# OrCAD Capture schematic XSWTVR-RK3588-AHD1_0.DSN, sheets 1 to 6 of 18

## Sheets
1 11 USB30 Port: size A3; rev: v1.0; company: yangdan; note: 11 USB30 Port; note: RK3588_AHD
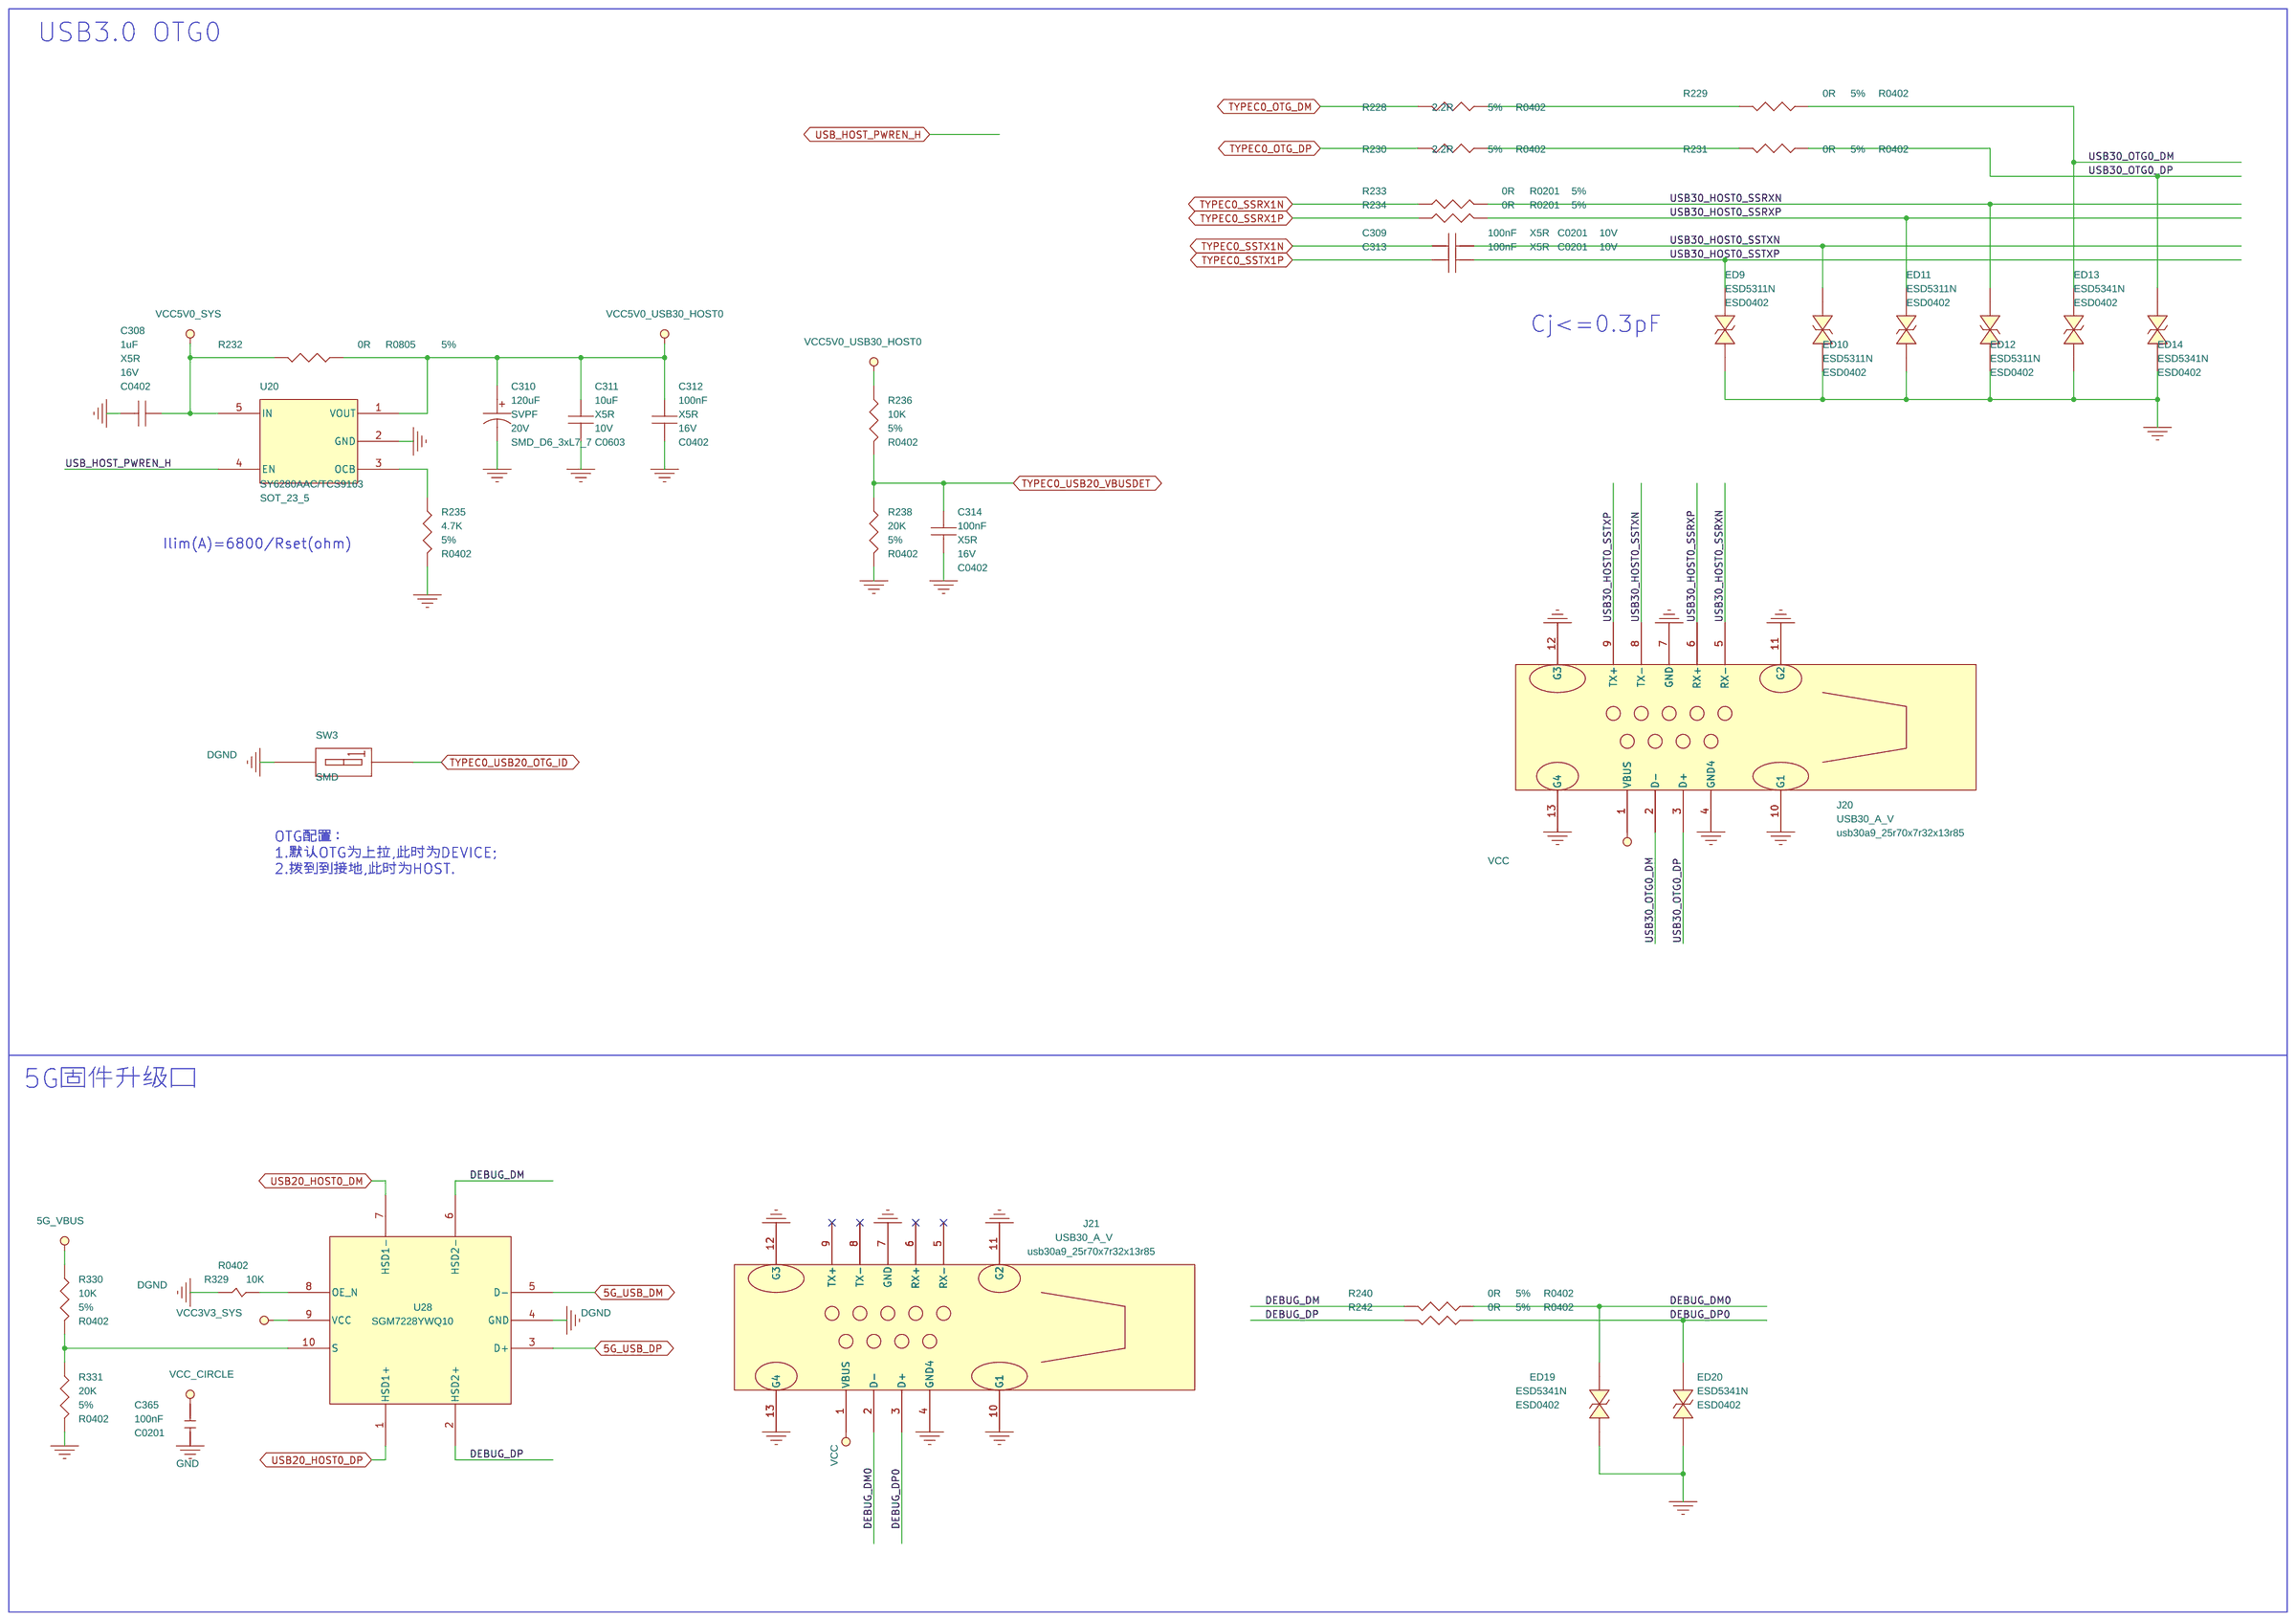
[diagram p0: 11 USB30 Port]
2 01 CORE_BROAD: size C; rev: V10; note: 01 CORE_BROAD
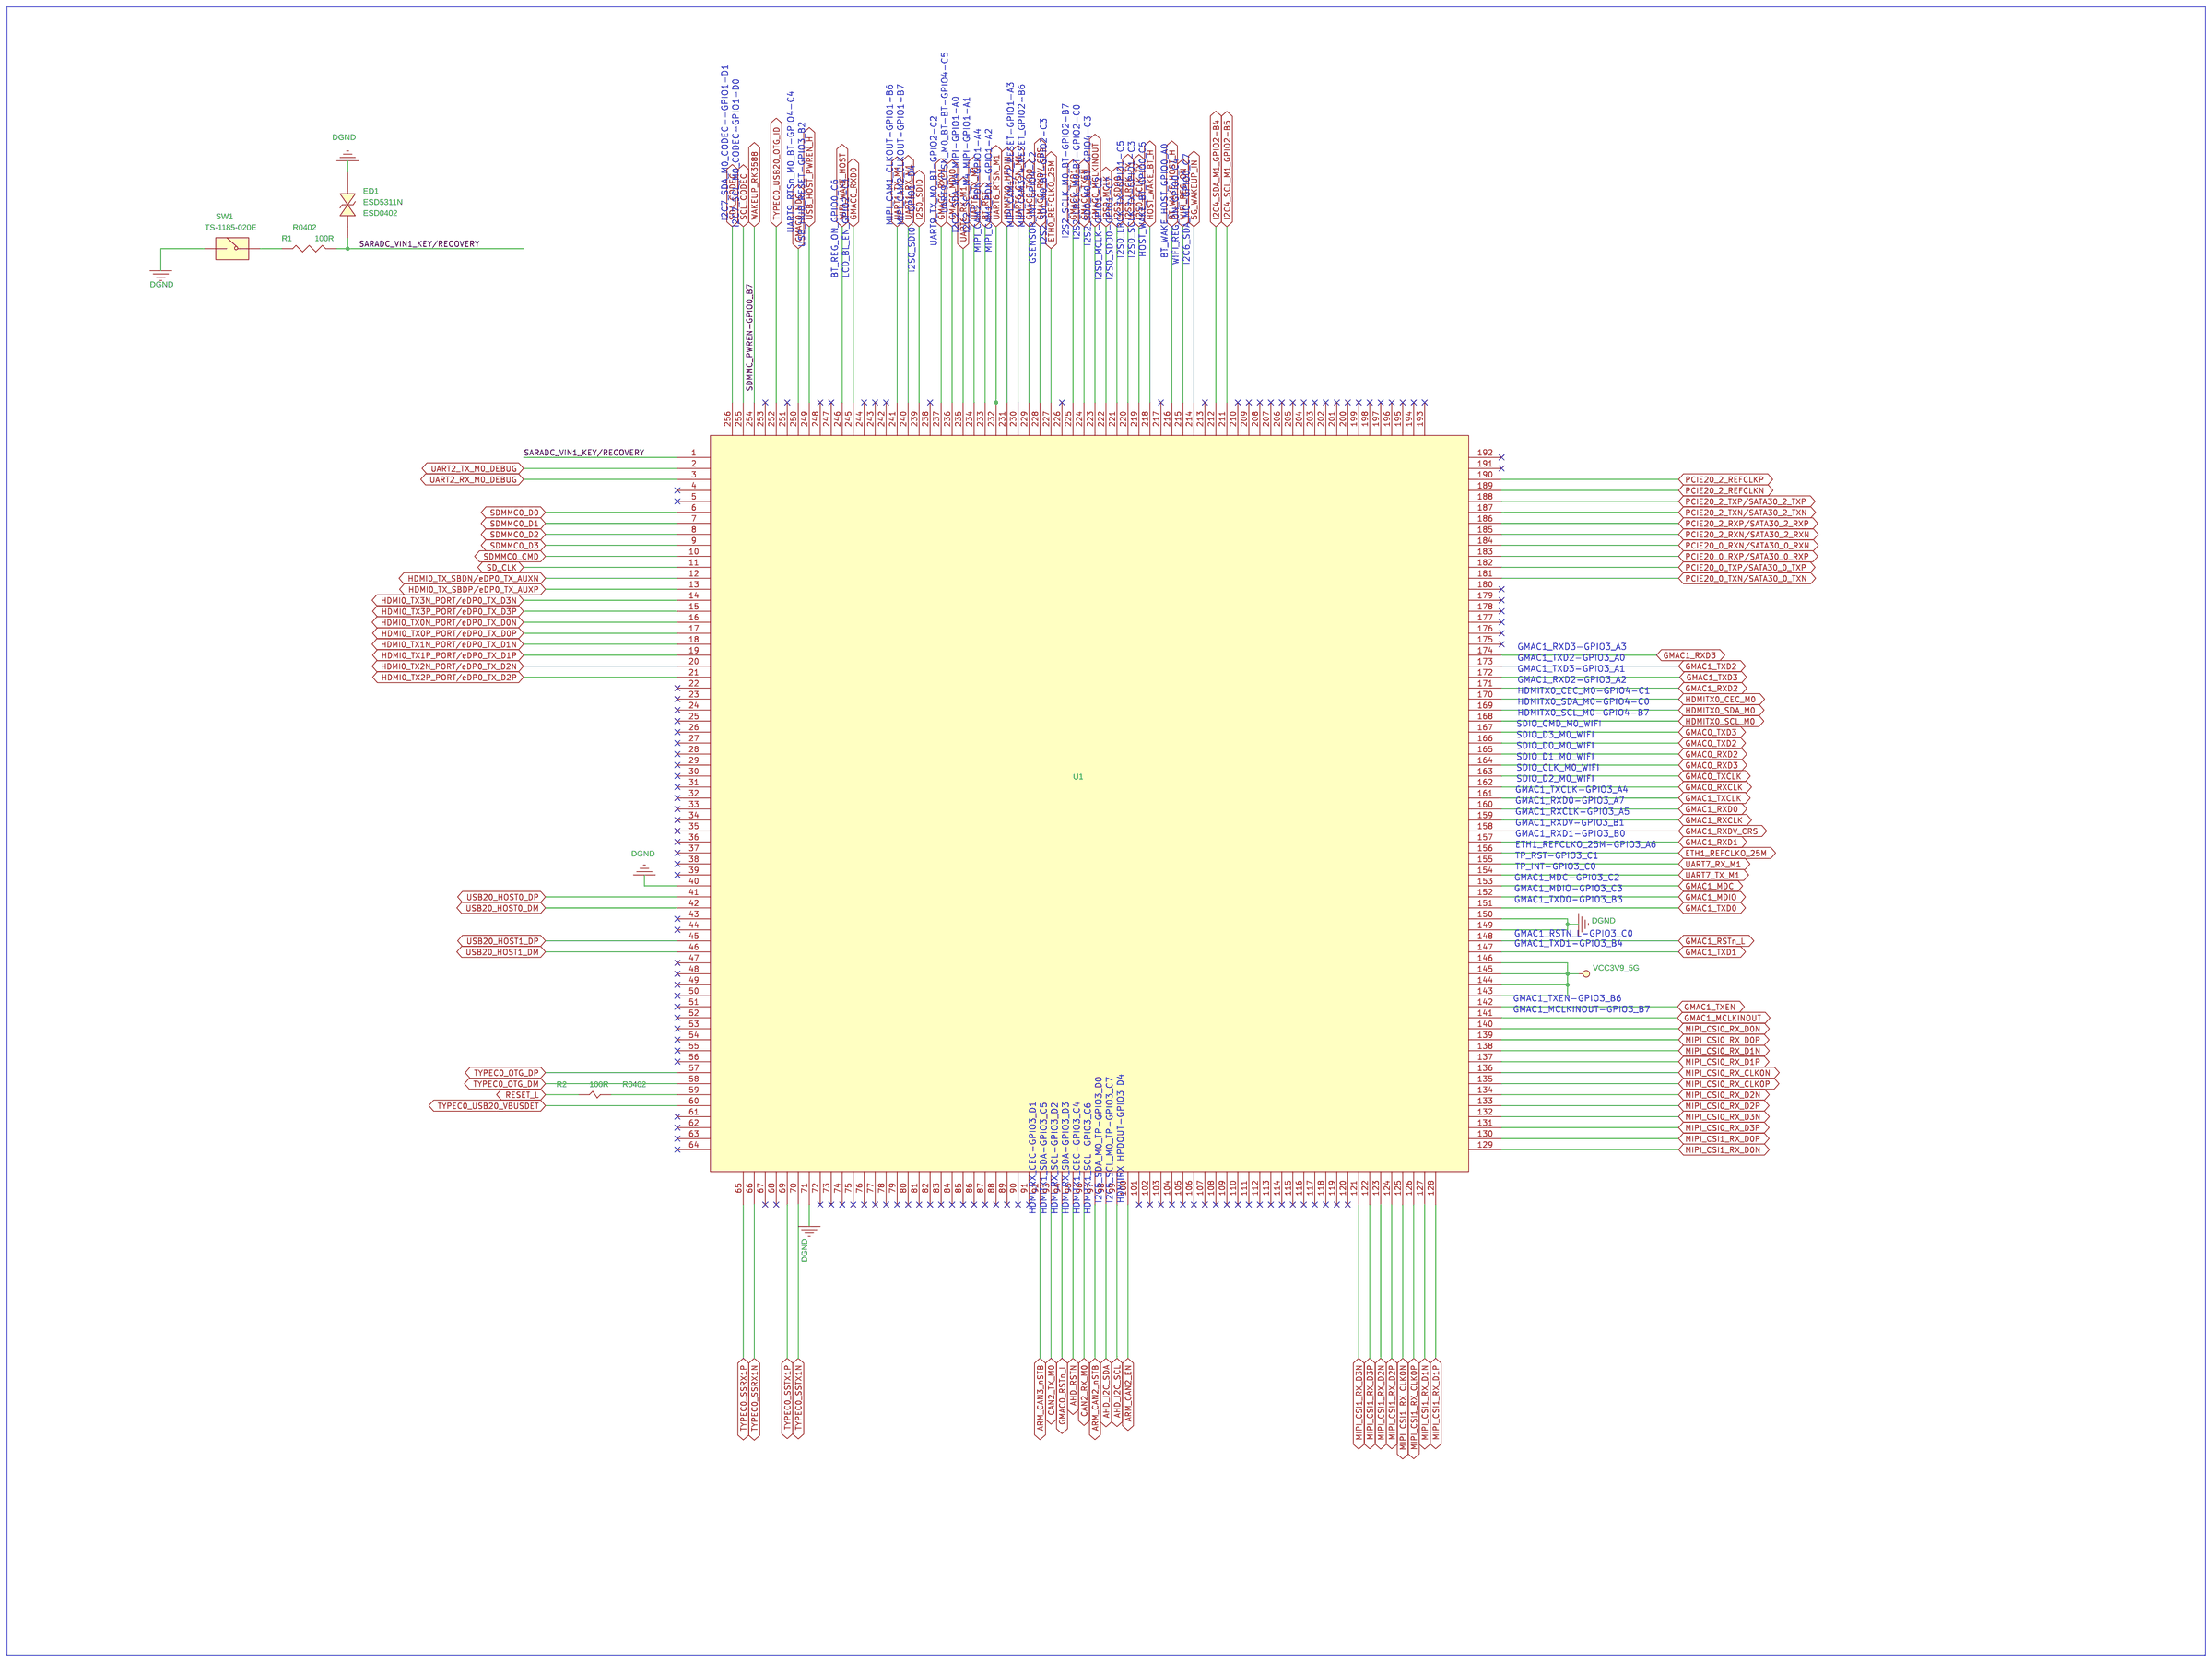
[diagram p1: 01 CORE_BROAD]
3 02 Power_DC IN: size Custom; note: 2 Power_DC IN
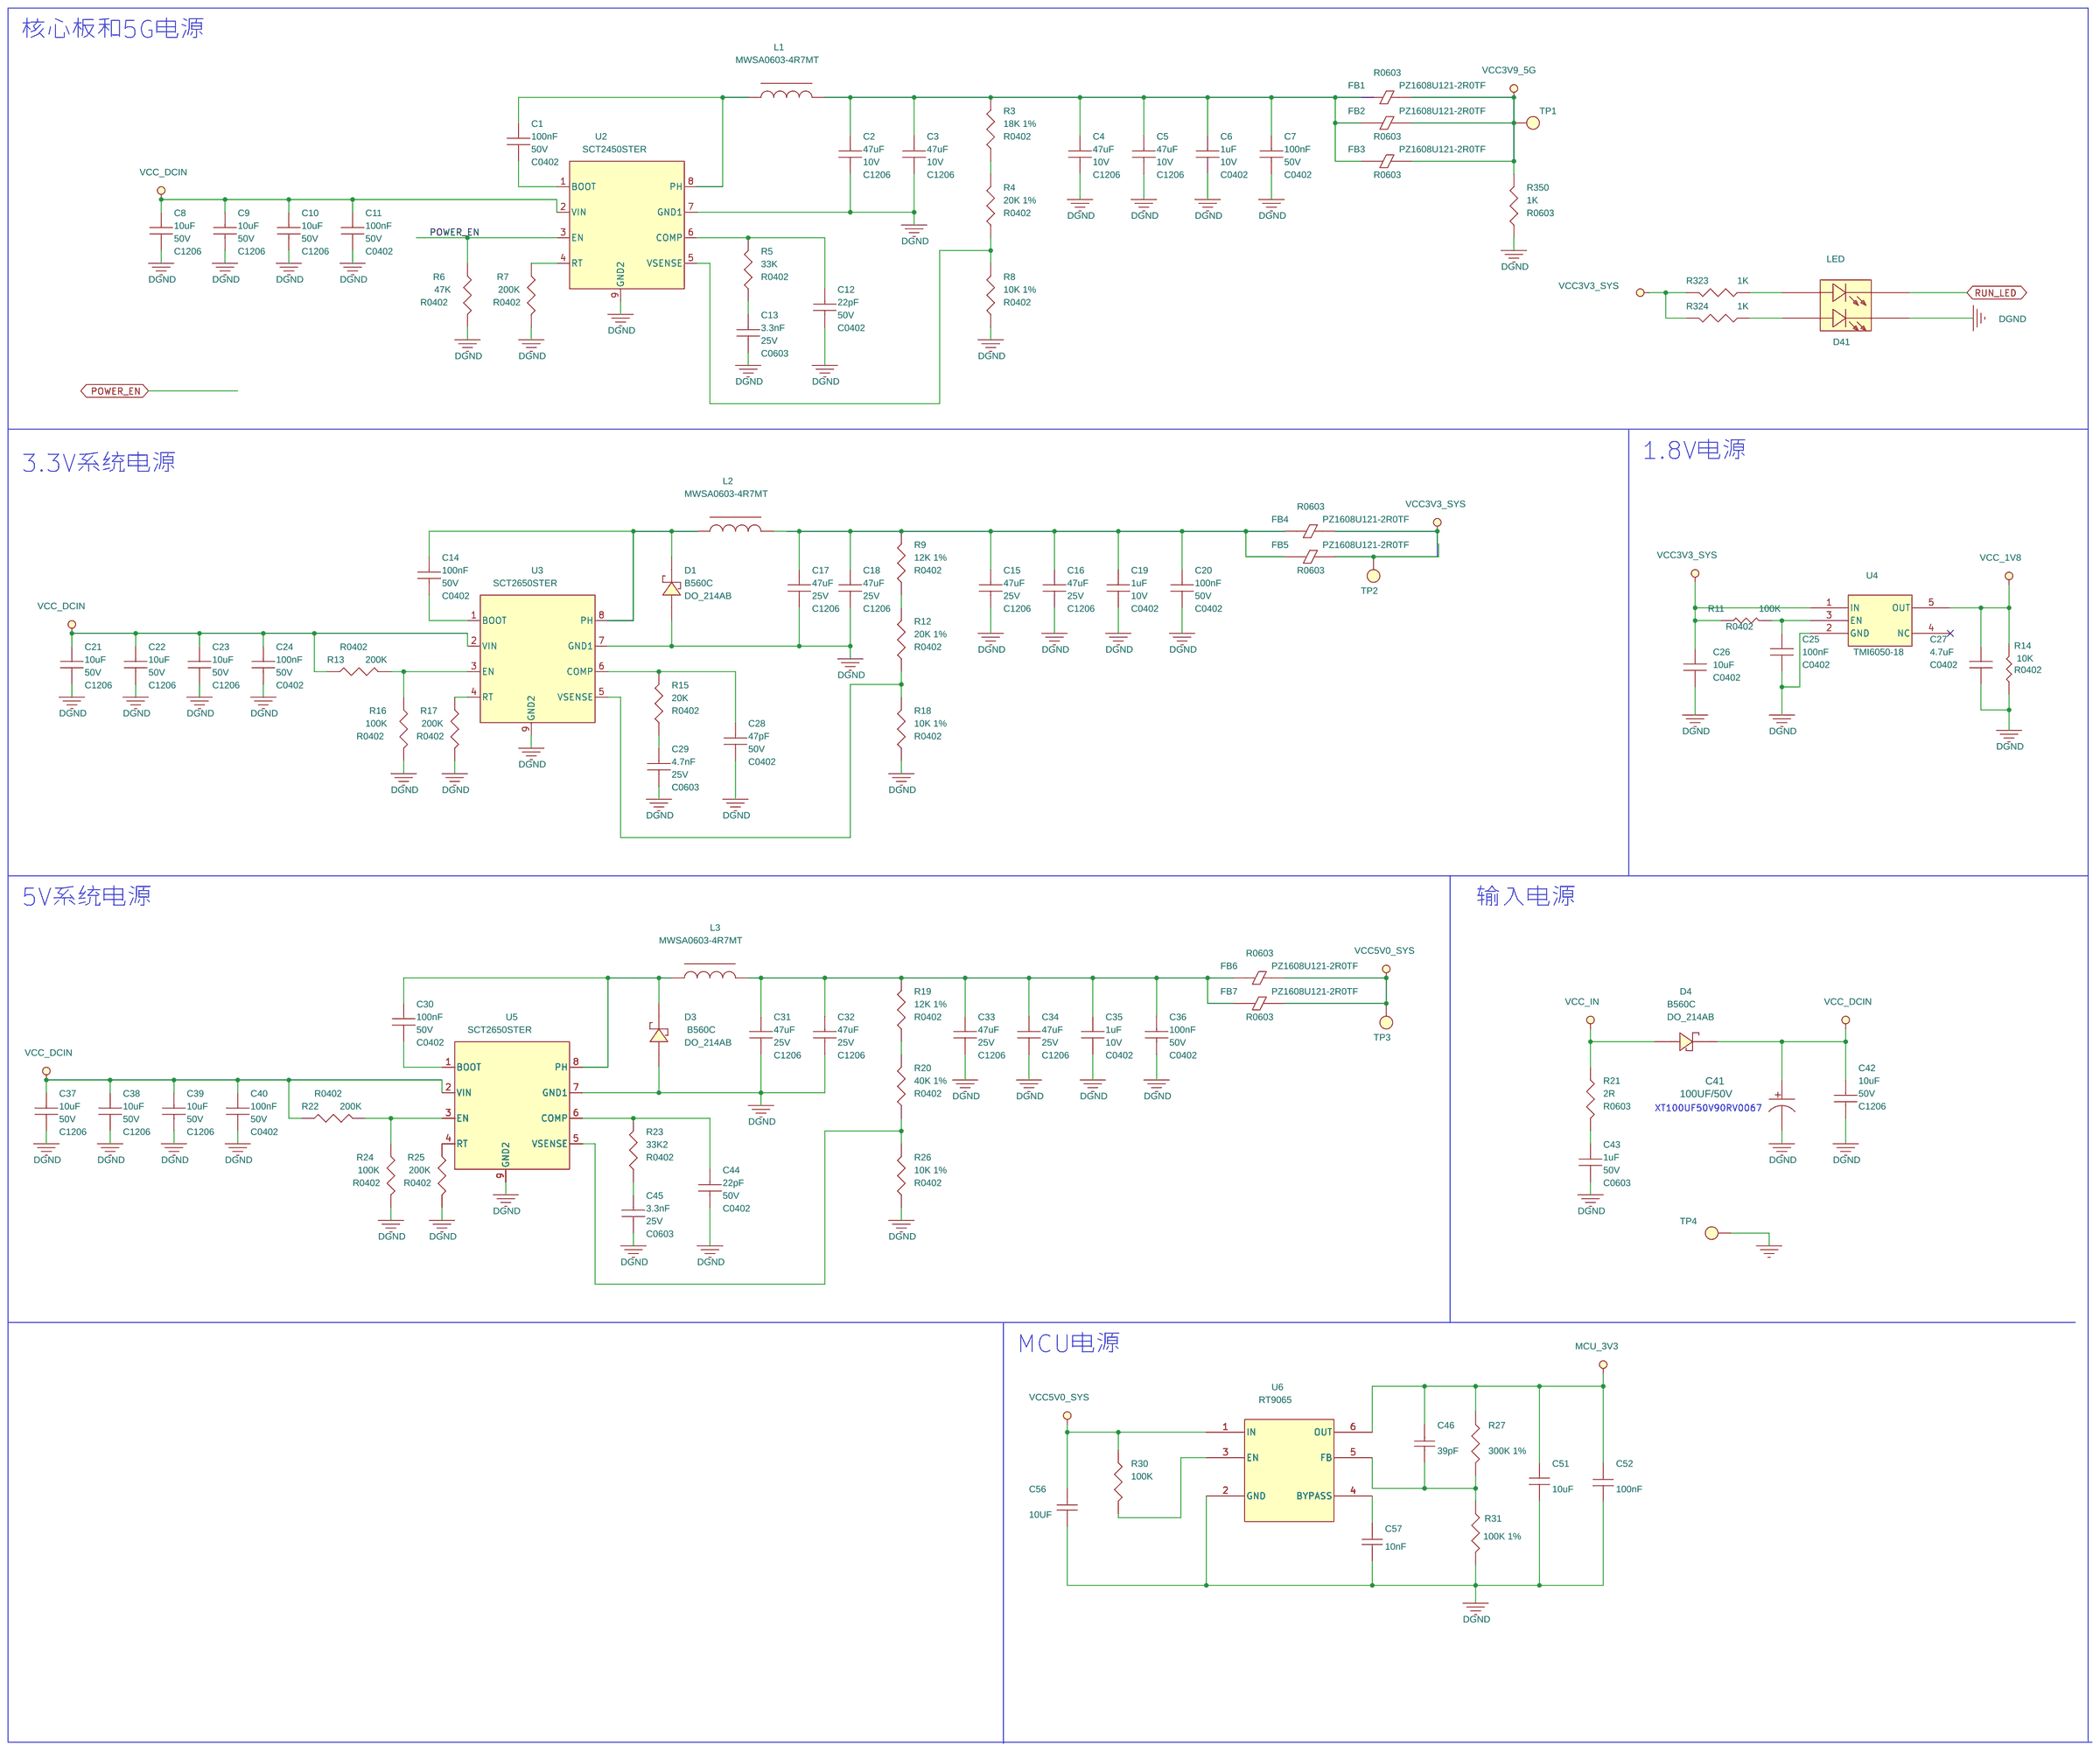
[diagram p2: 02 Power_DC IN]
4 03 MCU&MCU_CAN: size Custom; note: 03 MCU
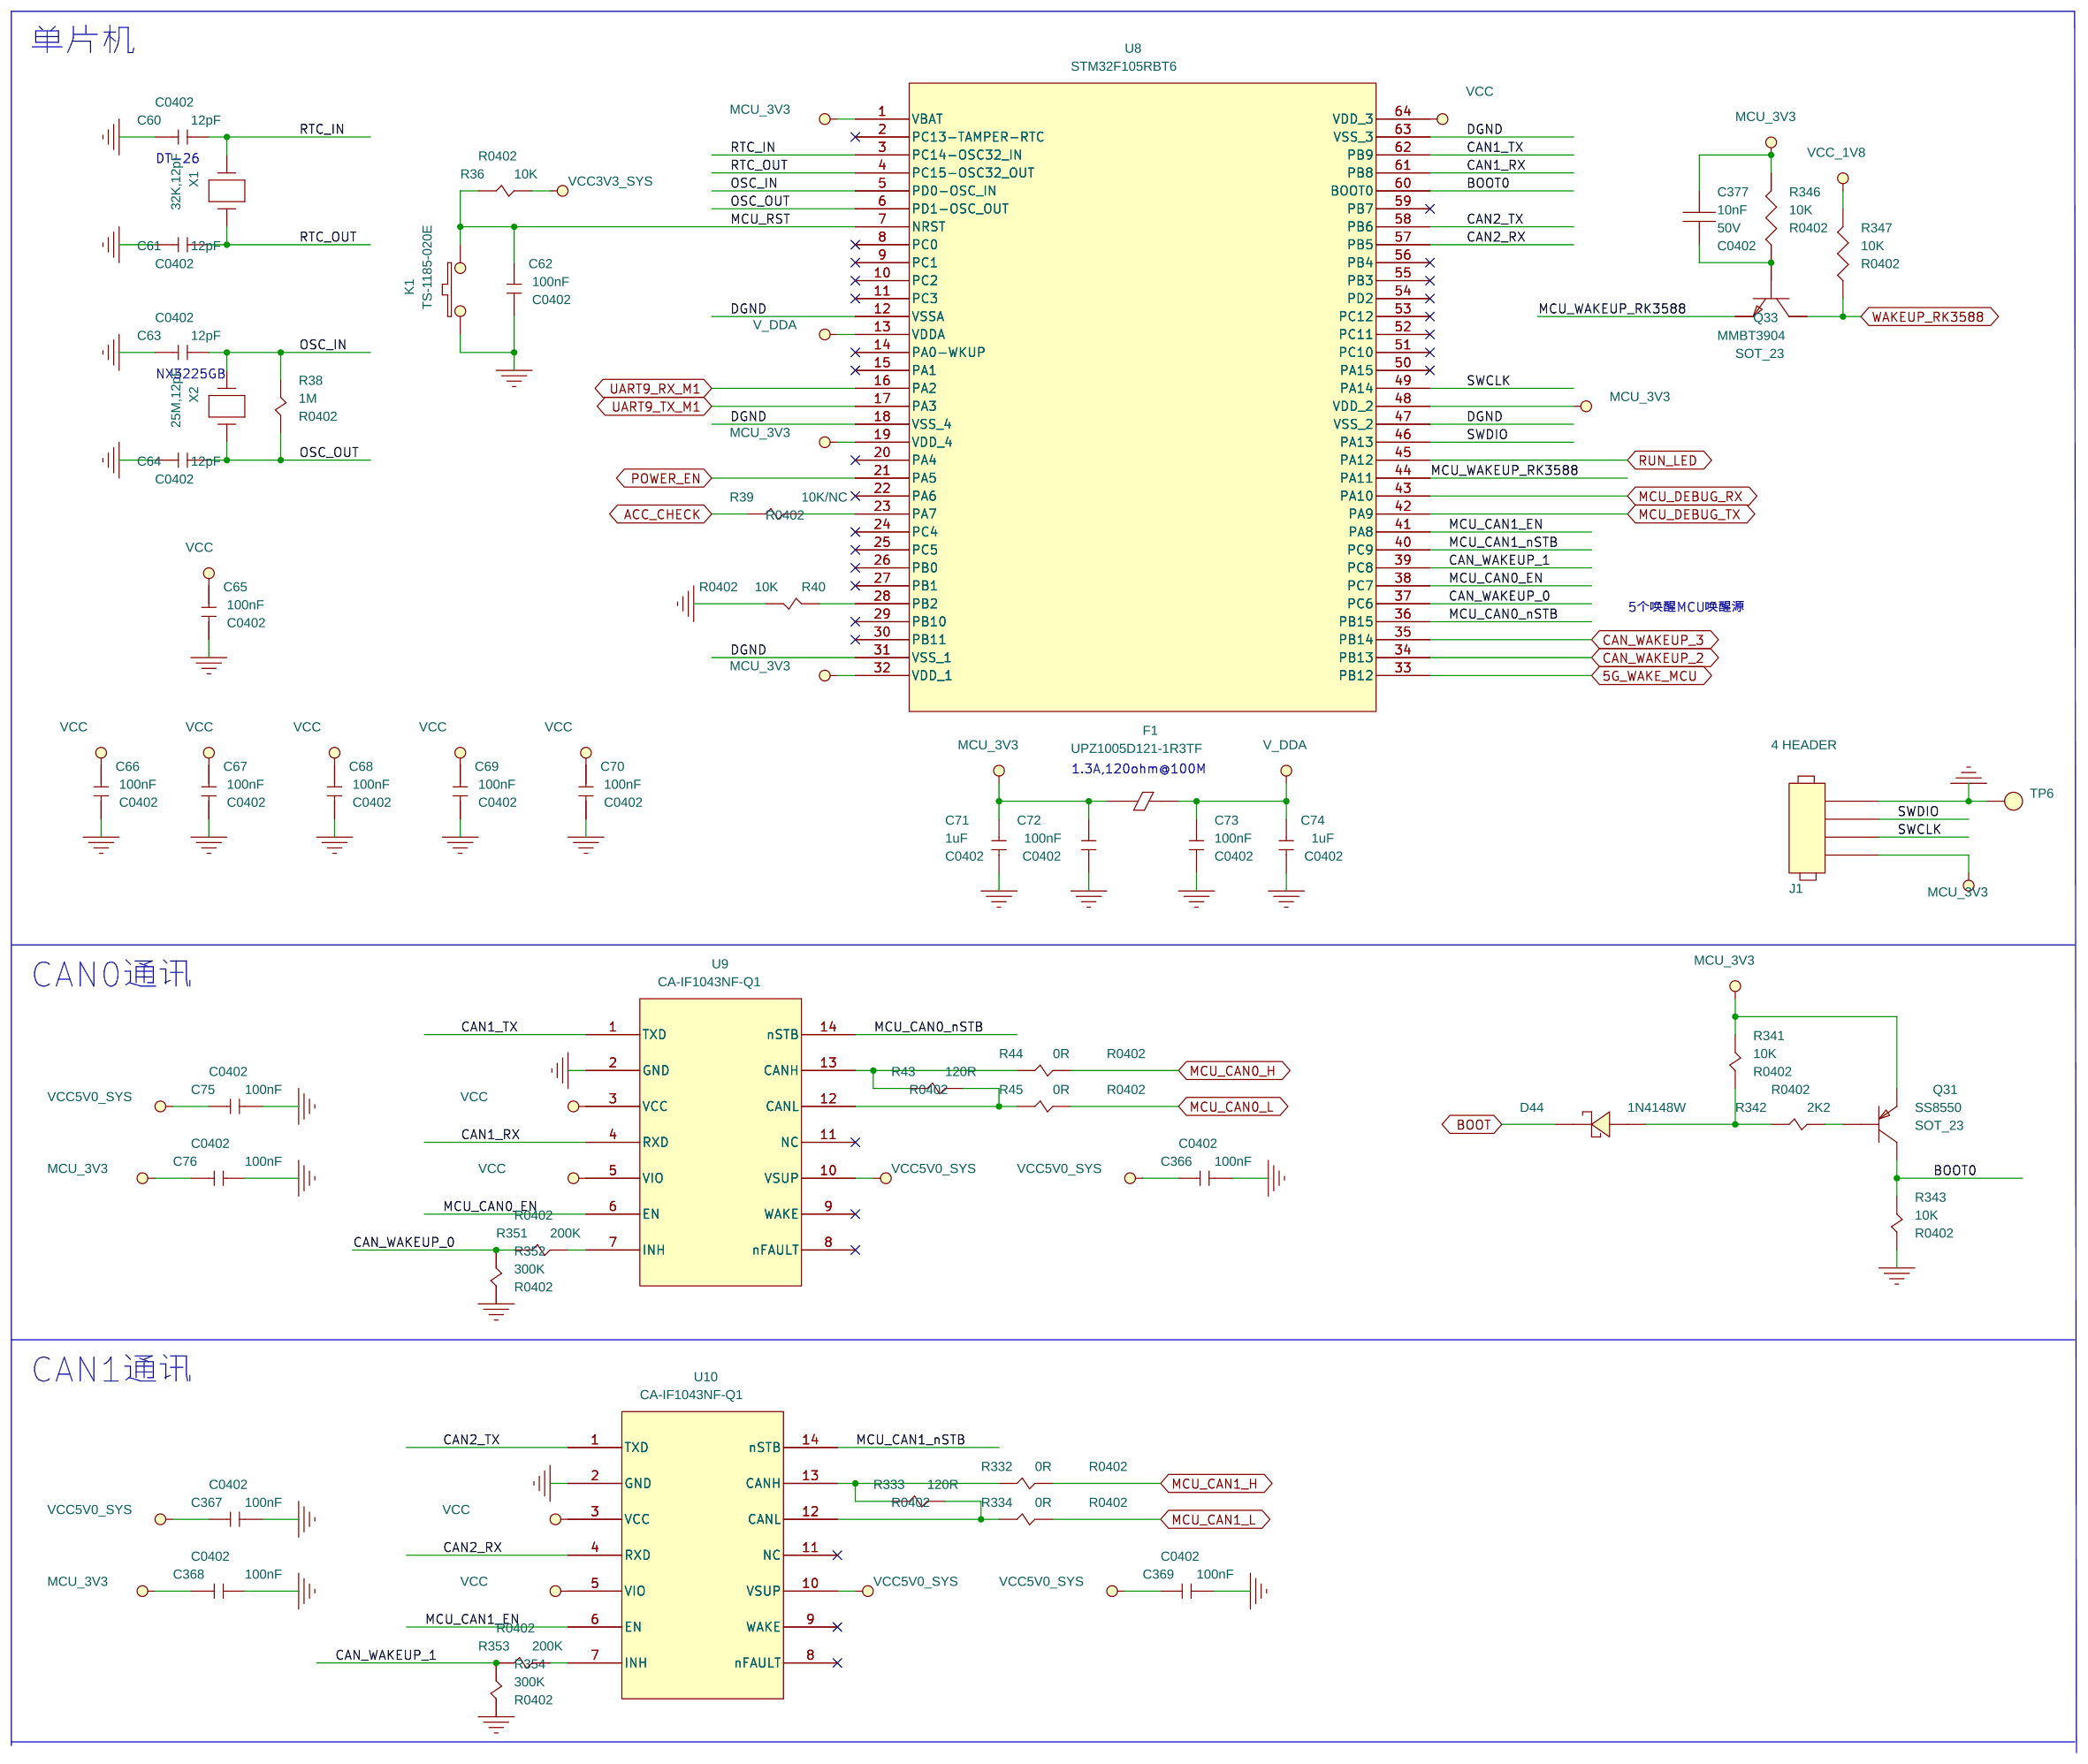
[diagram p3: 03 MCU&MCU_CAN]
5 04 M.2&5G: size Custom; note: 04 M.2&5G
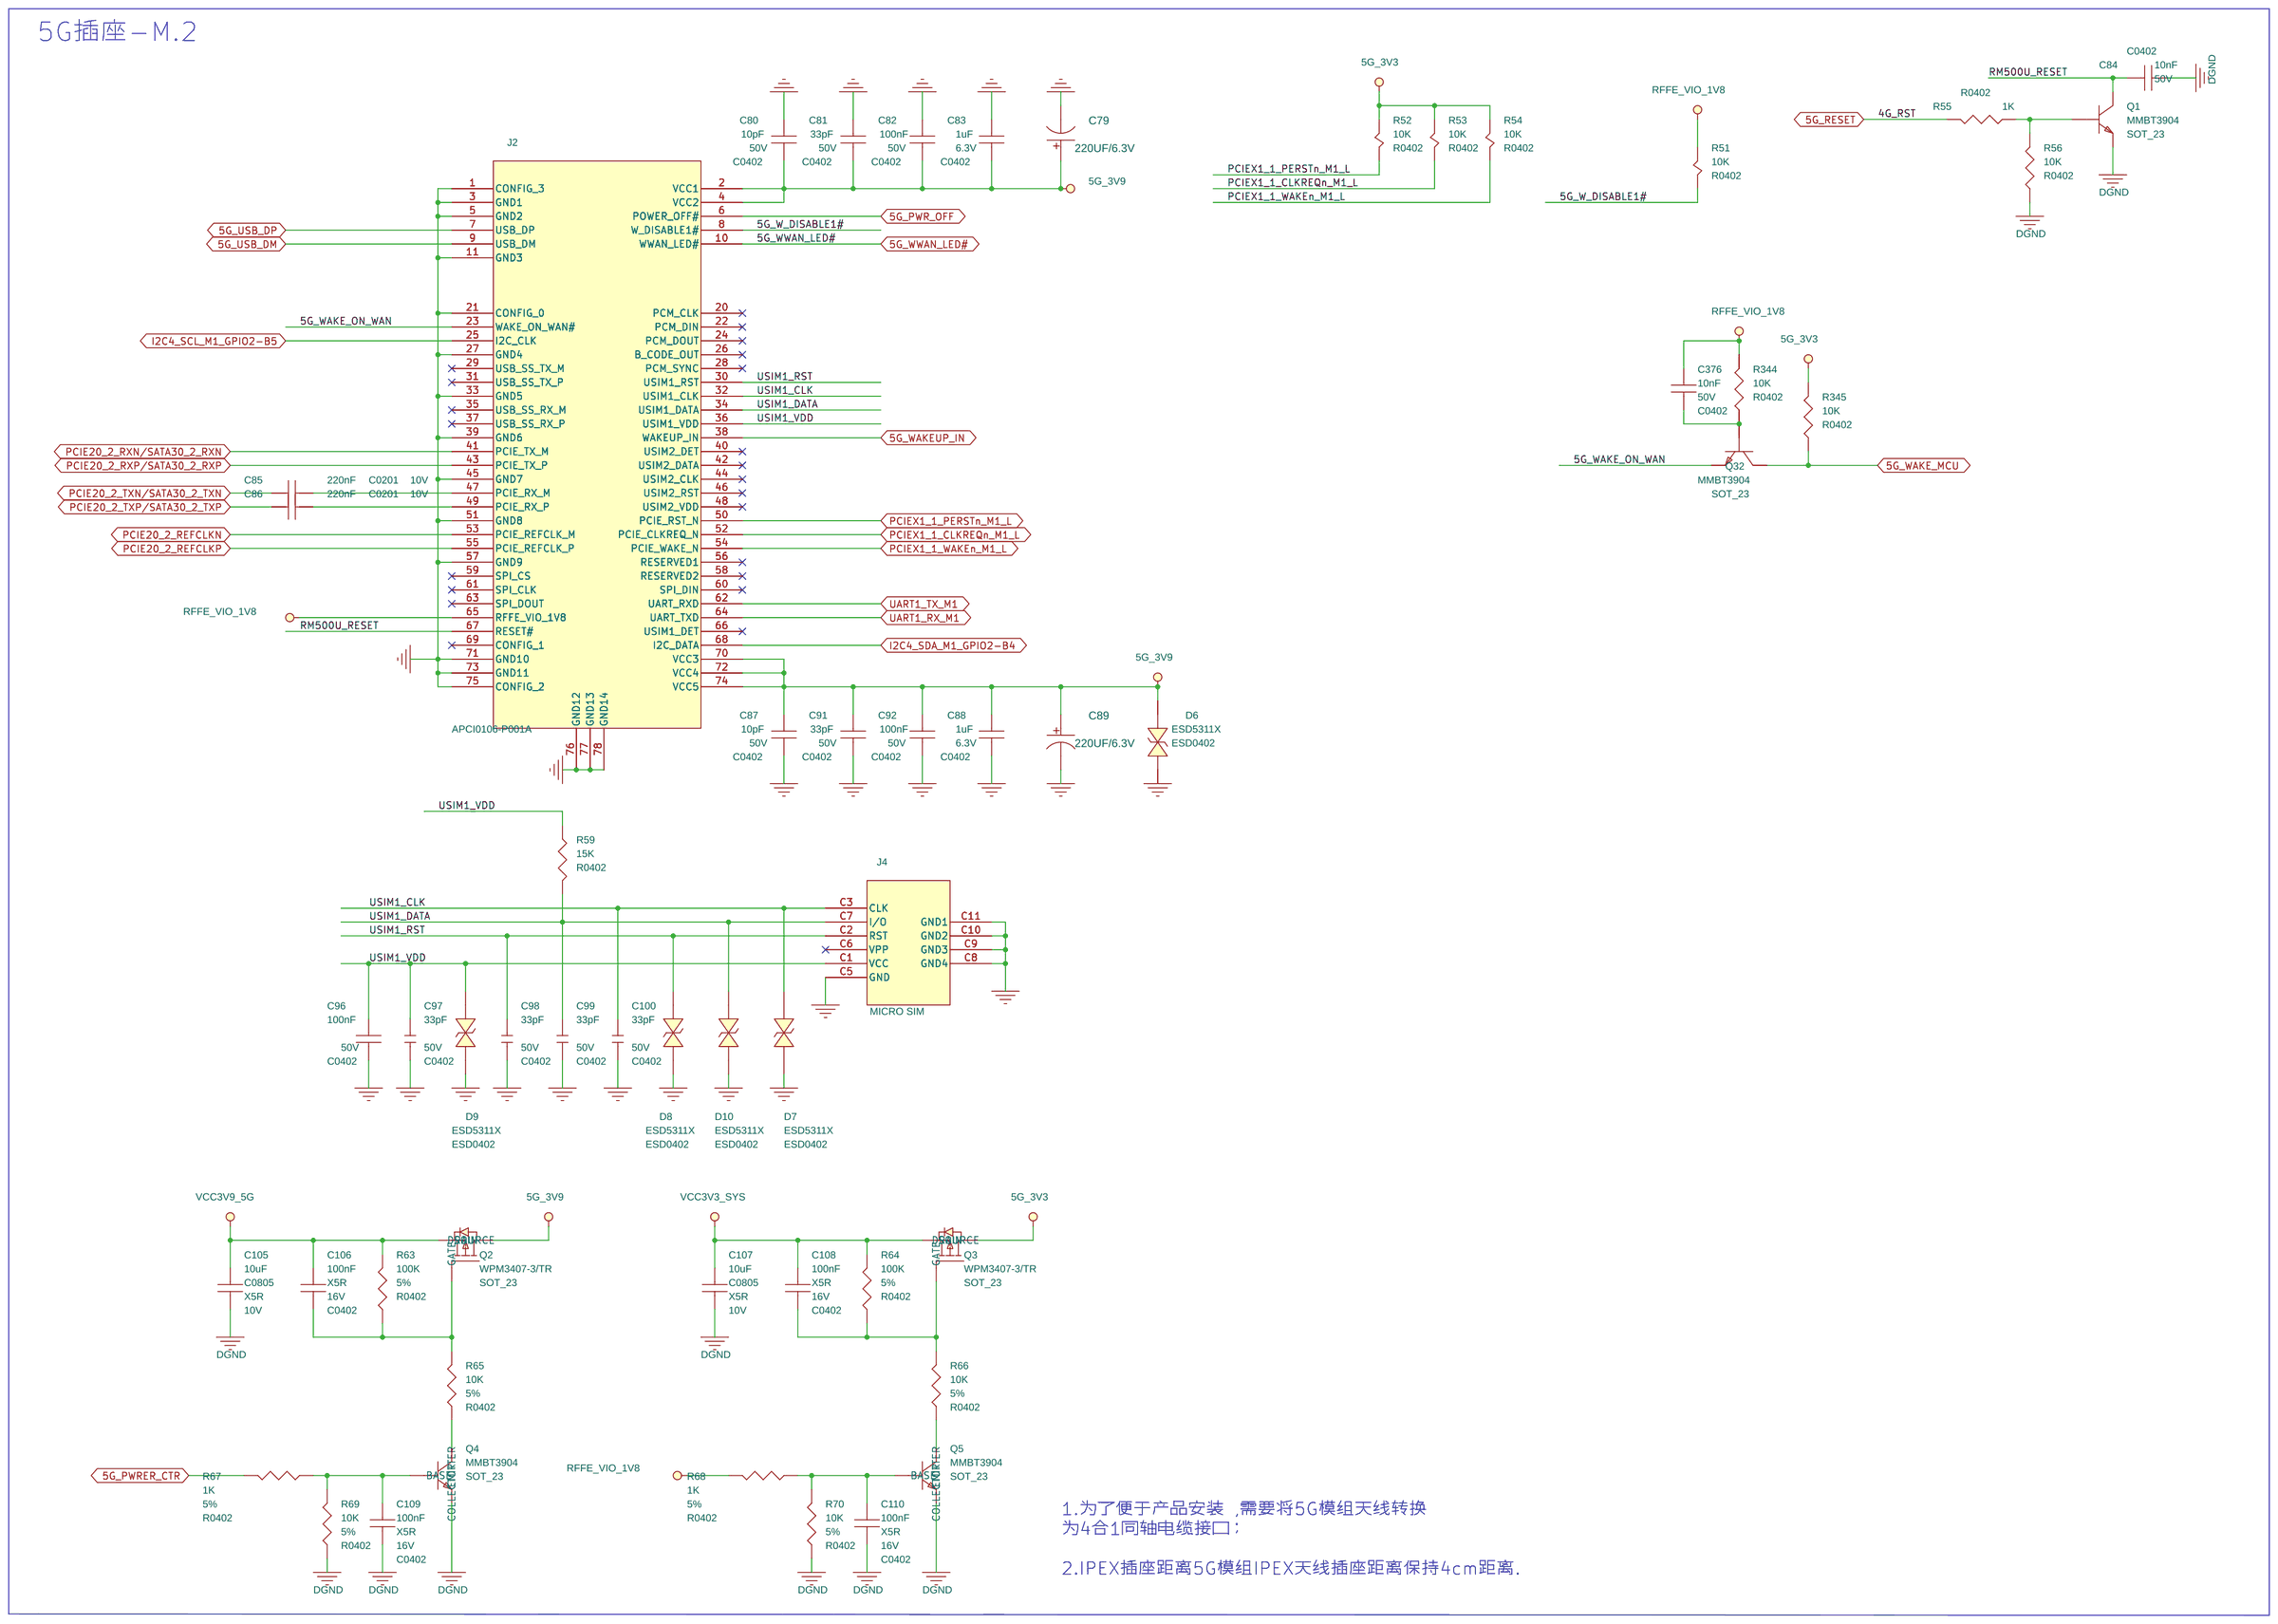
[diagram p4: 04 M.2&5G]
6 05 AHD-NVP6188A-01-04: size Custom; note: 05 AHD-NVP6188A
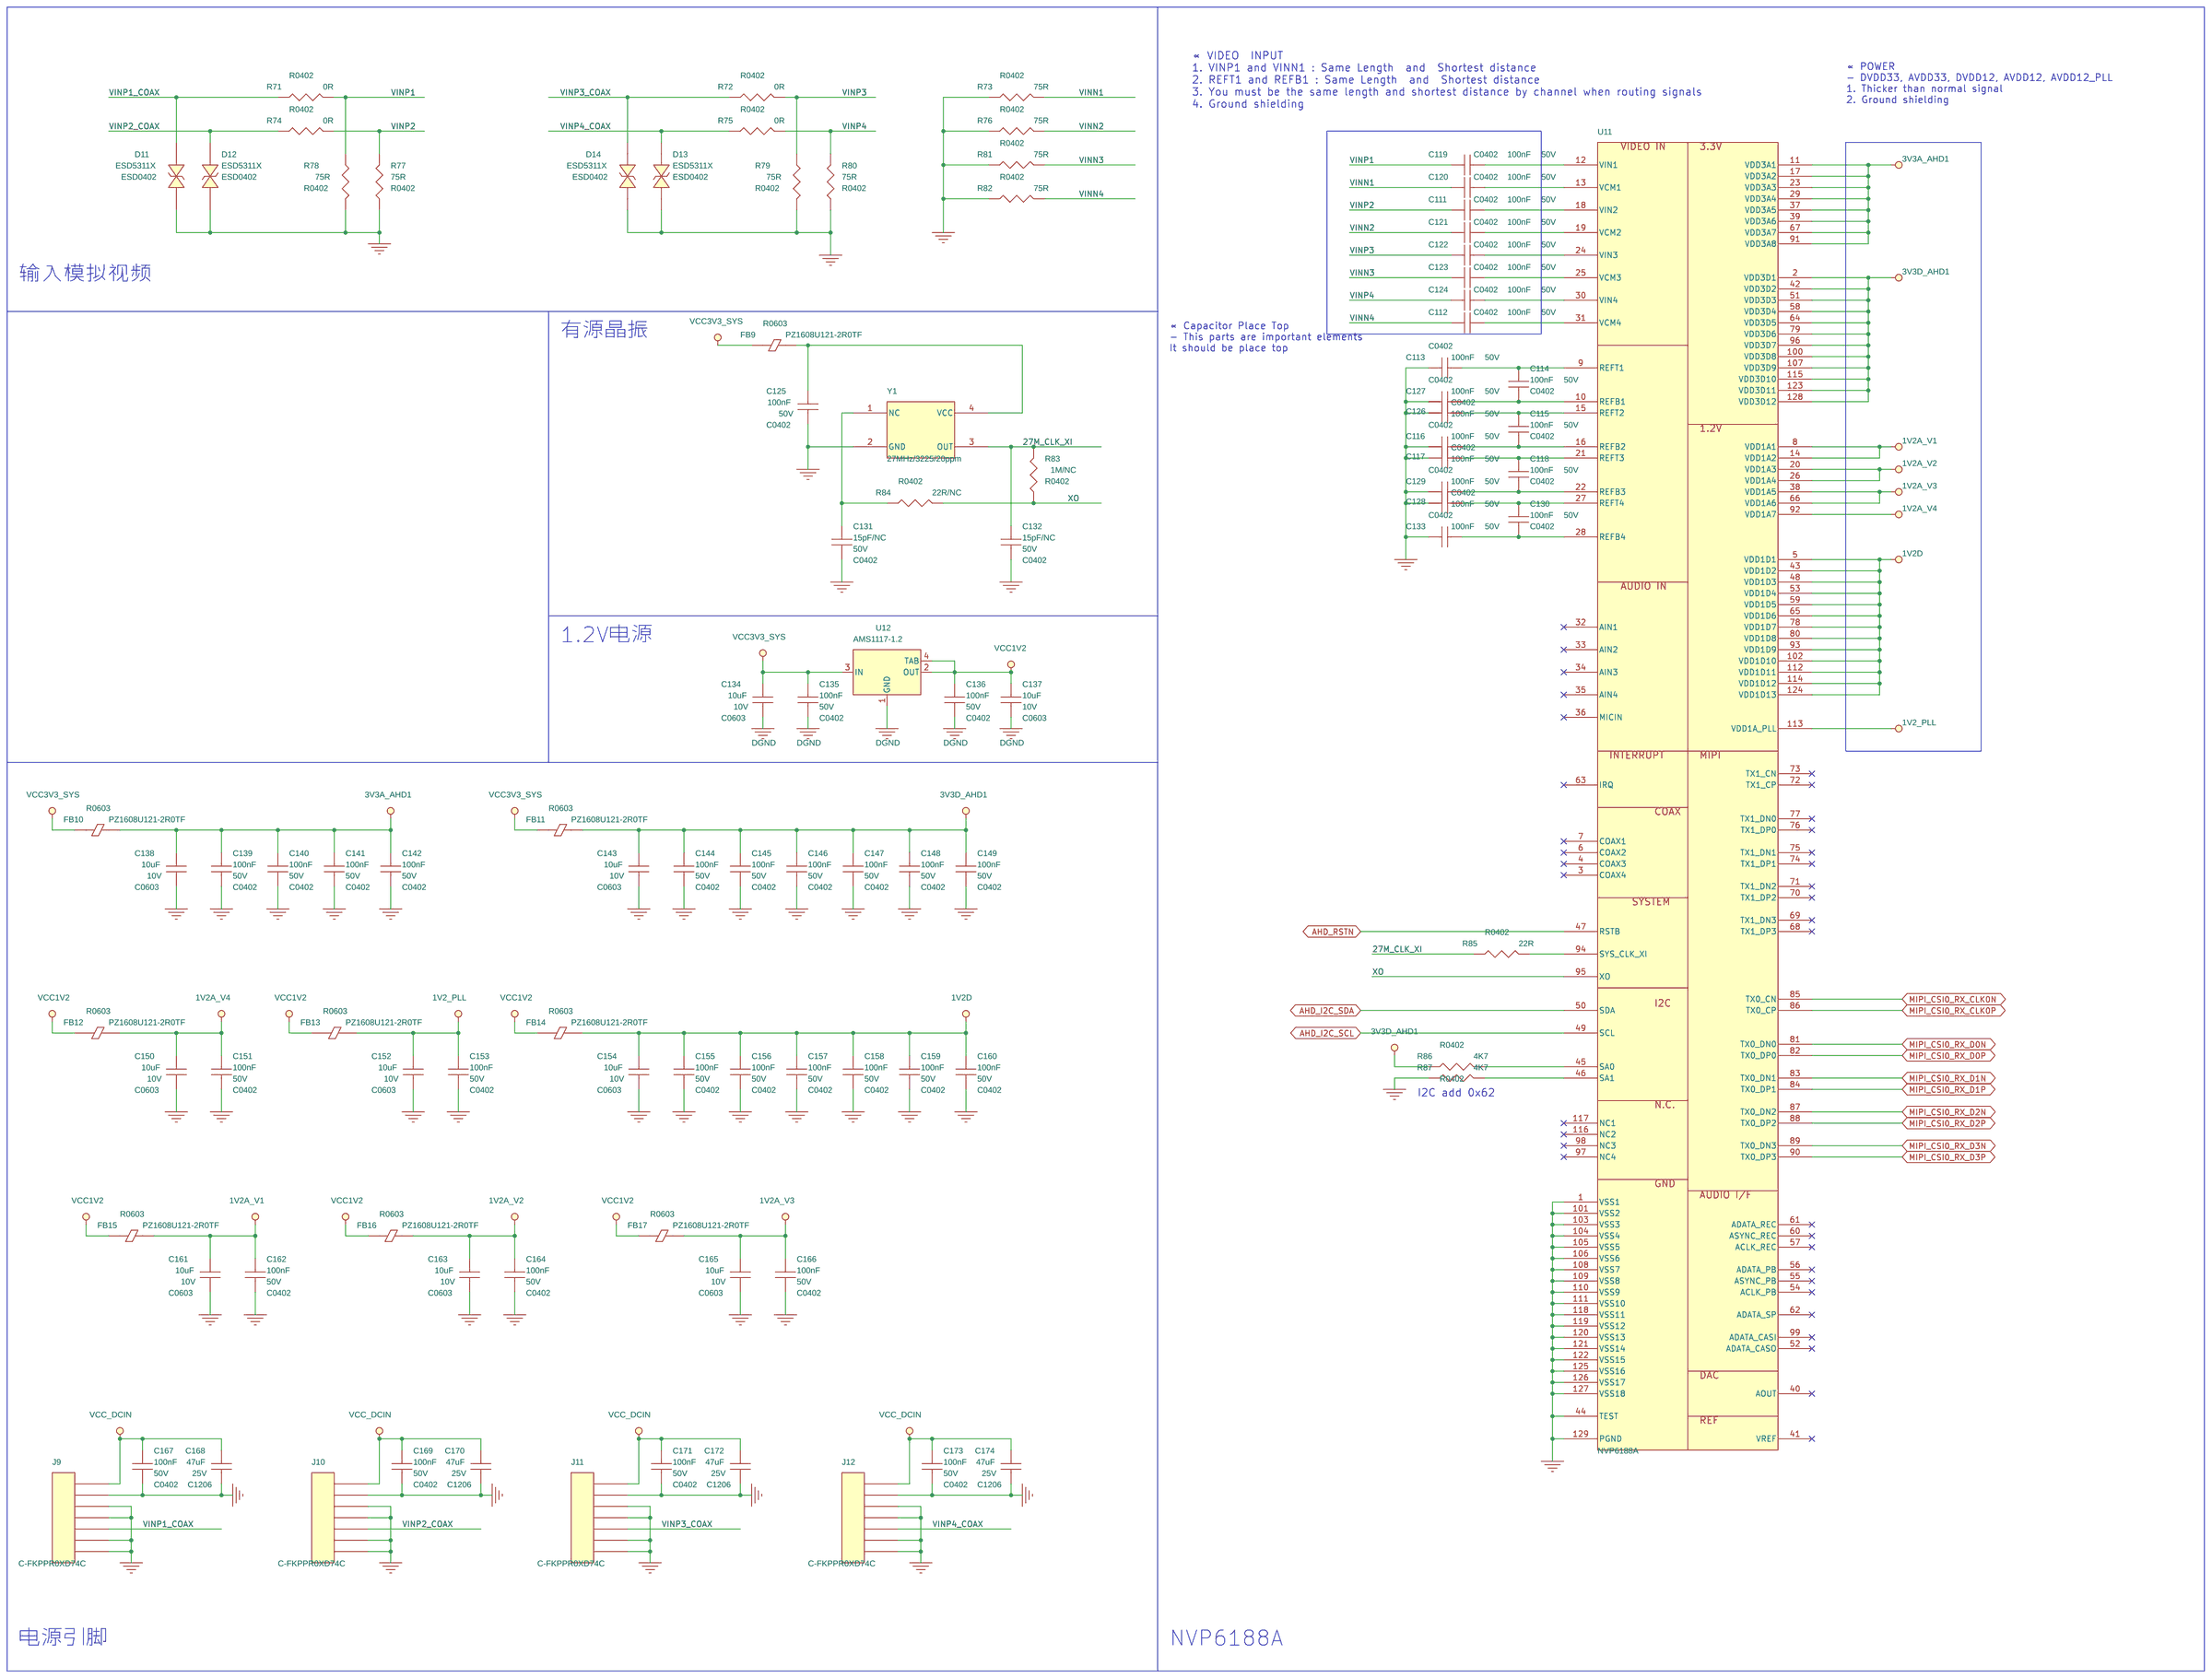
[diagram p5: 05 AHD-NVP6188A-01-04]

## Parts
sheet 01 CORE_BROAD
ED1  ESD5311N  [ESD0402]
R1  100R  [R0402]
R2  100R  [R0402]
SW1  TS-1185-020E  [SW_3p95mm_3p0mm]
U1  U1  [MODLE_65X65MM_256P]
sheet 02 Power_DC IN
C1  100nF  [C0402]
C2  47uF  [C1206]
C3  47uF  [C1206]
C4  47uF  [C1206]
C5  47uF  [C1206]
C6  1uF  [C0402]
C7  100nF  [C0402]
C8  10uF  [C1206]
C9  10uF  [C1206]
C10  10uF  [C1206]
C11  100nF  [C0402]
C12  22pF  [C0402]
C13  3.3nF  [C0603]
C14  100nF  [C0402]
C15  47uF  [C1206]
C16  47uF  [C1206]
C17  47uF  [C1206]
C18  47uF  [C1206]
C19  1uF  [C0402]
C20  100nF  [C0402]
C21  10uF  [C1206]
C22  10uF  [C1206]
C23  10uF  [C1206]
C24  100nF  [C0402]
C25  100nF  [C0402]
C26  10uF  [C0402]
C27  4.7uF  [C0402]
C28  47pF  [C0402]
C29  4.7nF  [C0603]
C30  100nF  [C0402]
C31  47uF  [C1206]
C32  47uF  [C1206]
C33  47uF  [C1206]
C34  47uF  [C1206]
C35  1uF  [C0402]
C36  100nF  [C0402]
C37  10uF  [C1206]
C38  10uF  [C1206]
C39  10uF  [C1206]
C40  100nF  [C0402]
C41  100UF/50V  [SMD_D8xL10_5mm]
C42  10uF  [C1206]
C43  1uF  [C0603]
C44  22pF  [C0402]
C45  3.3nF  [C0603]
C46  39pF  [C0402]
C51  10uF  [C0402]
C52  100nF  [C0402]
C56  10UF  [C0402]
C57  10nF  [C0402]
D1  B560C  [DO_214AB]
D3  B560C  [DO_214AB]
D4  B560C  [DO_214AB]
D41  LED  [LEDX2]
FB1  PZ1608U121-2R0TF  [R0603]
FB2  PZ1608U121-2R0TF  [R0603]
FB3  PZ1608U121-2R0TF  [R0603]
FB4  PZ1608U121-2R0TF  [R0603]
FB5  PZ1608U121-2R0TF  [R0603]
FB6  PZ1608U121-2R0TF  [R0603]
FB7  PZ1608U121-2R0TF  [R0603]
L1  MWSA0603-4R7MT  [L_6030]
L2  MWSA0603-4R7MT  [L_6030]
L3  MWSA0603-4R7MT  [L_6030]
R3  18K 1%  [R0402]
R4  20K 1%  [R0402]
R5  33K  [R0402]
R6  47K  [R0402]
R7  200K  [R0402]
R8  10K 1%  [R0402]
R9  12K 1%  [R0402]
R11  100K  [R0402]
R12  20K 1%  [R0402]
R13  200K  [R0402]
R14  10K  [R0402]
R15  20K  [R0402]
R16  100K  [R0402]
R17  200K  [R0402]
R18  10K 1%  [R0402]
R19  12K 1%  [R0402]
R20  40K 1%  [R0402]
R21  2R  [R0603]
R22  200K  [R0402]
R23  33K2  [R0402]
R24  100K  [R0402]
R25  200K  [R0402]
R26  10K 1%  [R0402]
R27  300K 1%  [R0402]
R30  100K  [R0402]
R31  100K 1%  [R0402]
R323  1K  [R0402]
R324  1K  [R0402]
R350  1K  [R0603]
TP1  TP  [TP_1_0]
TP2  TP  [TP_1_0]
TP3  TP  [TP_1_0]
TP4  TP  [TP_1_0]
U2  SCT2450STER  [IC_SOP8_PAD]
U3  SCT2650STER  [IC_SOP8_PAD]
U4  TMI6050-18  [SOT_23_5]
U5  SCT2650STER  [IC_SOP8_PAD]
U6  RT9065  [IC_SOT23_6]
sheet 03 MCU&MCU_CAN
C60  12pF  [C0402]
C61  12pF  [C0402]
C62  100nF  [C0402]
C63  12pF  [C0402]
C64  12pF  [C0402]
C65  100nF  [C0402]
C66  100nF  [C0402]
C67  100nF  [C0402]
C68  100nF  [C0402]
C69  100nF  [C0402]
C70  100nF  [C0402]
C71  1uF  [C0402]
C72  100nF  [C0402]
C73  100nF  [C0402]
C74  1uF  [C0402]
C75  100nF  [C0402]
C76  100nF  [C0402]
C366  100nF  [C0402]
C367  100nF  [C0402]
C368  100nF  [C0402]
C369  100nF  [C0402]
C377  10nF  [C0402]
D44  1N4148W  [SOD_123]
F1  UPZ1005D121-1R3TF  [R0402]
J1  4 HEADER  [SOCKET_4P_2P54]
K1  TS-1185-020E  [SW_3p95mm_3p0mm]
Q31  SS8550  [SOT_23]
Q33  MMBT3904  [SOT_23]
R36  10K  [R0402]
R38  1M  [R0402]
R39  10K/NC  [R0402]
R40  10K  [R0402]
R43  120R  [R0402]
R44  0R  [R0402]
R45  0R  [R0402]
R332  0R  [R0402]
R333  120R  [R0402]
R334  0R  [R0402]
R341  10K  [R0402]
R342  2K2  [R0402]
R343  10K  [R0402]
R346  10K  [R0402]
R347  10K  [R0402]
R351  200K  [R0402]
R352  300K  [R0402]
R353  200K  [R0402]
R354  300K  [R0402]
TP6  TP  [TP_1_0]
U8  STM32F105RBT6  [IC_QFN64_STM32]
U9  CA-IF1043NF-Q1  [IC_SOIC_14]
U10  CA-IF1043NF-Q1  [IC_SOIC_14]
X1  32K,12pF  [X_3215_2P]
X2  25M,12pF  [X_3225_2P]
sheet 04 M.2&5G
C79  220UF/6.3V  [T_3528]
C80  10pF  [C0402]
C81  33pF  [C0402]
C82  100nF  [C0402]
C83  1uF  [C0402]
C84  10nF  [C0402]
C85  220nF  [C0201]
C86  220nF  [C0201]
C87  10pF  [C0402]
C88  1uF  [C0402]
C89  220UF/6.3V  [T_3528]
C91  33pF  [C0402]
C92  100nF  [C0402]
C96  100nF  [C0402]
C97  33pF  [C0402]
C98  33pF  [C0402]
C99  33pF  [C0402]
C100  33pF  [C0402]
C105  10uF  [C0805]
C106  100nF  [C0402]
C107  10uF  [C0805]
C108  100nF  [C0402]
C109  100nF  [C0402]
C110  100nF  [C0402]
C376  10nF  [C0402]
D6  ESD5311X  [ESD0402]
D7  ESD5311X  [ESD0402]
D8  ESD5311X  [ESD0402]
D9  ESD5311X  [ESD0402]
D10  ESD5311X  [ESD0402]
J2  APCI0106-P001A  [M2_M_KEY]
J4  MICRO SIM  [SIM_002_P6]
Q1  MMBT3904  [SOT_23]
Q2  WPM3407-3/TR  [SOT_23]
Q3  WPM3407-3/TR  [SOT_23]
Q4  MMBT3904  [SOT_23]
Q5  MMBT3904  [SOT_23]
Q32  MMBT3904  [SOT_23]
R51  10K  [R0402]
R52  10K  [R0402]
R53  10K  [R0402]
R54  10K  [R0402]
R55  1K  [R0402]
R56  10K  [R0402]
R59  15K  [R0402]
R63  100K  [R0402]
R64  100K  [R0402]
R65  10K  [R0402]
R66  10K  [R0402]
R67  1K  [R0402]
R68  1K  [R0402]
R69  10K  [R0402]
R70  10K  [R0402]
R344  10K  [R0402]
R345  10K  [R0402]
sheet 05 AHD-NVP6188A-01-04
C111  100nF  [C0402]
C112  100nF  [C0402]
C113  100nF  [C0402]
C114  100nF  [C0402]
C115  100nF  [C0402]
C116  100nF  [C0402]
C117  100nF  [C0402]
C118  100nF  [C0402]
C119  100nF  [C0402]
C120  100nF  [C0402]
C121  100nF  [C0402]
C122  100nF  [C0402]
C123  100nF  [C0402]
C124  100nF  [C0402]
C125  100nF  [C0402]
C126  100nF  [C0402]
C127  100nF  [C0402]
C128  100nF  [C0402]
C129  100nF  [C0402]
C130  100nF  [C0402]
C131  15pF/NC  [C0402]
C132  15pF/NC  [C0402]
C133  100nF  [C0402]
C134  10uF  [C0603]
C135  100nF  [C0402]
C136  100nF  [C0402]
C137  10uF  [C0603]
C138  10uF  [C0603]
C139  100nF  [C0402]
C140  100nF  [C0402]
C141  100nF  [C0402]
C142  100nF  [C0402]
C143  10uF  [C0603]
C144  100nF  [C0402]
C145  100nF  [C0402]
C146  100nF  [C0402]
C147  100nF  [C0402]
C148  100nF  [C0402]
C149  100nF  [C0402]
C150  10uF  [C0603]
C151  100nF  [C0402]
C152  10uF  [C0603]
C153  100nF  [C0402]
C154  10uF  [C0603]
C155  100nF  [C0402]
C156  100nF  [C0402]
C157  100nF  [C0402]
C158  100nF  [C0402]
C159  100nF  [C0402]
C160  100nF  [C0402]
C161  10uF  [C0603]
C162  100nF  [C0402]
C163  10uF  [C0603]
C164  100nF  [C0402]
C165  10uF  [C0603]
C166  100nF  [C0402]
C167  100nF  [C0402]
C168  47uF  [C1206]
C169  100nF  [C0402]
C170  47uF  [C1206]
C171  100nF  [C0402]
C172  47uF  [C1206]
C173  100nF  [C0402]
C174  47uF  [C1206]
D11  ESD5311X  [ESD0402]
D12  ESD5311X  [ESD0402]
D13  ESD5311X  [ESD0402]
D14  ESD5311X  [ESD0402]
FB9  PZ1608U121-2R0TF  [R0603]
FB10  PZ1608U121-2R0TF  [R0603]
FB11  PZ1608U121-2R0TF  [R0603]
FB12  PZ1608U121-2R0TF  [R0603]
FB13  PZ1608U121-2R0TF  [R0603]
FB14  PZ1608U121-2R0TF  [R0603]
FB15  PZ1608U121-2R0TF  [R0603]
FB16  PZ1608U121-2R0TF  [R0603]
FB17  PZ1608U121-2R0TF  [R0603]
J9  C-FKPPR0XD74C  [C_FKPPR0XD]
J10  C-FKPPR0XD74C  [C_FKPPR0XD]
J11  C-FKPPR0XD74C  [C_FKPPR0XD]
J12  C-FKPPR0XD74C  [C_FKPPR0XD]
R71  0R  [R0402]
R72  0R  [R0402]
R73  75R  [R0402]
R74  0R  [R0402]
R75  0R  [R0402]
R76  75R  [R0402]
R77  75R  [R0402]
R78  75R  [R0402]
R79  75R  [R0402]
R80  75R  [R0402]
R81  75R  [R0402]
R82  75R  [R0402]
R83  1M/NC  [R0402]
R84  22R/NC  [R0402]
R85  22R  [R0402]
R86  4K7  [R0402]
R87  4K7  [R0402]
U11  NVP6188A  [IC_TQFP128]
U12  AMS1117-1.2  [IC_SOT_223_1p2V]
Y1  27MHz/3225/20ppm  [X_3225]
sheet 11 USB30 Port
C308  1uF  [C0402]
C309  100nF  [C0201]
C310  120uF  [SMD_D6_3xL7_7]
C311  10uF  [C0603]
C312  100nF  [C0402]
C313  100nF  [C0201]
C314  100nF  [C0402]
C365  100nF  [C0201]
ED9  ESD5311N  [ESD0402]
ED10  ESD5311N  [ESD0402]
ED11  ESD5311N  [ESD0402]
ED12  ESD5311N  [ESD0402]
ED13  ESD5341N  [ESD0402]
ED14  ESD5341N  [ESD0402]
ED19  ESD5341N  [ESD0402]
ED20  ESD5341N  [ESD0402]
J20  USB30_A_V  [usb30a9_25r70x7r32x13r85]
J21  USB30_A_V  [usb30a9_25r70x7r32x13r85]
R228  2.2R  [R0402]
R229  0R  [R0402]
R230  2.2R  [R0402]
R231  0R  [R0402]
R232  0R  [R0805]
R233  0R  [R0201]
R234  0R  [R0201]
R235  4.7K  [R0402]
R236  10K  [R0402]
R238  20K  [R0402]
R240  0R  [R0402]
R242  0R  [R0402]
R329  10K  [R0402]
R330  10K  [R0402]
R331  20K  [R0402]
SW3  SMD  [SMD_2P_5P4x2P9mm]
U20  SY6280AAC/TCS9163  [SOT_23_5]
U28  SGM7228YWQ10  [IC_WQFN_10]

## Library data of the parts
ED1 ED9-ED12 = DIODE_BI_DIR_TRIG: 1-Line, Bi-directional, Transient Voltage Suppressors.0.25pF.; Created by: JJJ; Manufacturer: WillSemi(韦尔半导体); Part Type: ESD_TVS; Priority: A
R1 R3-R9 R12 R13 R15-R20 R22-R26 R350 = RESISTOR_0: 通用厚膜电阻,232K,+/-1%,R0402,1/16W.; Created by: YTL; Manufacturer: YAGEO; Manufacturer PN: RC0402FR-07232KL; Part Type: 通用厚膜电阻; Priority: A; RK PN: RC0402FR-07232KL; Tolerance: 5%; Wattage: 1/16W
R2 R36 R38-R40 R43-R45 R51-R54 R329 R332-R334 R341-R343 R351-R354 = SR_1: price: 0.000688
SW1 = CAP_NP_20
U1 = U1_0
C1 C11 C14 C24 C30 C40 C135 C136 C139-C142 C144-C149 C151 C153 C155-C160 C162 C164 C166 = CAP_NP_0: cap,10.00uF,+/-10%,25V,X5R,C1206; C_Voltage: 6.3V; Created by: JJJ; Dielectric: X5R; Manufacturer: TDK; Manufacturer PN: C3216X5R1E106K085AC; Part Type: C1206; Priority: A; RK PN: C3216X5R1E106K085AC; Tolerance: 10%; Voltage: 50V
C2-C5 = CAP_NP_0: cap,10.00uF,+/-10%,25V,X5R,C1206; C_Voltage: 6.3V; Created by: JJJ; Dielectric: X5R; Manufacturer: TDK; Manufacturer PN: C3216X5R1E106K085AC; Priority: A; RK PN: C3216X5R1E106K085AC; Tolerance: 10%; Voltage: 10V
C6 C19 C35 = CAP_NP_11: cap,100.00nF,+/-10%,50V,X5R,C0603; Created by: JJJ; Dielectric: X5R; Manufacturer: TDK; Manufacturer PN: C1608X5R1H104K080AA; Part Type: C0603; Priority: A; RK PN: C1608X5R1H104K080AA; Tolerance: 10%; Voltage: 10V
C7 C20 C36 C167 C169 C171 C173 = CAP_NP_11: cap,100.00nF,+/-10%,50V,X5R,C0603; Created by: JJJ; Dielectric: X5R; Manufacturer: TDK; Manufacturer PN: C1608X5R1H104K080AA; Part Type: C0603; Priority: A; RK PN: C1608X5R1H104K080AA; Tolerance: 10%; Voltage: 50V
C8-C10 C21-C23 C37-C39 = CAP_NP_0: cap,10.00uF,+/-10%,25V,X5R,C1206; C_Voltage: 6.3V; Created by: JJJ; Dielectric: X5R; Manufacturer: TDK; Manufacturer PN: C3216X5R1E106K085AC; Priority: A; RK PN: C3216X5R1E106K085AC; Tolerance: 10%; Voltage: 50V
C12 C28 C44 C80-C82 C87 C91 C92 = CAP_NP_0: cap,22.00pF,+/-5%,50V,C0G,C0402; Created by: JJJ; Dielectric: C0G; Manufacturer: TDK; Manufacturer PN: C1005C0G1H220J050BA; Priority: A; RK PN: C1005C0G1H220J050BA; Tolerance: 5%; Voltage: 50V
C13 C29 C45 = CAP_NP_0: cap,10.00uF,+/-10%,25V,X5R,C1206; C_Voltage: 6.3V; Created by: JJJ; Dielectric: X5R; Manufacturer: TDK; Manufacturer PN: C3216X5R1E106K085AC; Part Type: C1206; Priority: A; RK PN: C3216X5R1E106K085AC; Tolerance: 10%; Voltage: 25V
C15-C18 C31-C34 C168 C170 C172 C174 = CAP_NP_0: cap,10.00uF,+/-10%,25V,X5R,C1206; C_Voltage: 6.3V; Created by: JJJ; Dielectric: X5R; Manufacturer: TDK; Manufacturer PN: C3216X5R1E106K085AC; Priority: A; RK PN: C3216X5R1E106K085AC; Tolerance: 10%; Voltage: 25V
C25 = CAP_v2: Capacitor-100nF,+/-10%,X5R,25V-0402; Part Number: 02.0038.00; Part Type: 0402表贴普通电容; 供应商: 国巨 / Murata; 供应商1: Eyang; 规格型号1: CC0402KRX5R8BB104 / GRM155R71E104KE14D; 联系人: 谢苏云; 联系人1: 何俊; 手机: 15900554174; 手机1: 18317187178; 邮箱: susan.xie@murata.com; 邮箱1: hejunxs@szeyang.com
C26 = CAP_v2: Capacitor-10uF,+/-20%,X5R,6.3V-0402+; Part Number: 02.0034.00; Part Type: 0402表贴普通电容; 供应商: 国巨 / Murata; 规格型号1: CC0402MRX5R5BB106 / GRM155R60J106ME44D; 联系人: 谢苏云; 手机: 15900554174; 邮箱: susan.xie@murata.com
C27 = CAP_v2: Capacitor-4.7uF,+/-20%,X5R,6.3V-0402; Part Number: 02.0018.00; Part Type: 0402表贴普通电容; 供应商: 国巨 / Murata; 规格型号1: CC0402MRX5R5BB475 / GRM153R60J475ME15D; 联系人: 谢苏云; 手机: 15900554174; 邮箱: susan.xie@murata.com
C41 C79 C89 = CP_0: %182%%238%%182%%168%%185%%164%%215%%247%%181%%231%%209%%185%(V): 16; %195%%232%%202%%246%: 非固体SMD铝电容-16V-100UF-+/-20%-6.3*5.4MM-极性-105DEGC-1000H-片式,温度敏感器件-工艺耐温250DEGC,5S; %208%%161%%192%%224%%195%%251%%179%%198%: 非固体SMD铝电容; CODE: 8010269; COMPONENT_HIGH_MAX: 5.7MM; PKG_TYPE: SAC6666
C42 = CAP_NP_11: cap,10.00uF,+/-10%,25V,X5R,C1206; C_Voltage: 6.3V; Created by: JJJ; Dielectric: X5R; Manufacturer: TDK; Manufacturer PN: C3216X5R1E106K085AC; Priority: A; RK PN: C3216X5R1E106K085AC; Tolerance: 10%; Voltage: 50V
C43 = CAP_NP_11: cap,2.20uF,+/-10%,25V,X5R,C1206; Created by: JJJ; Dielectric: X5R; Manufacturer: TDK; Manufacturer PN: C3216X5R1E225K160AA; Part Type: C1206; Priority: A; RK PN: C3216X5R1E225K160AA; Tolerance: 10%; Voltage: 50V
C46 C56 C57 = CAP_0805: CAP 100nF 25V X7R 20% 0603 SMD; 01 IPN: 17-604100; 02 DESC: CAP, 0.1uF/25V 0603; 03 MAN: AVX; 04 MPN: 06035G104ZAT; 20 PACKAGE: 0603C; 21 FOOTPRINT: 0603C; Installation: ON; Material NO.: C01-104258060; REUSE_ANNOTATE: TRUE
C51 = SC10U10V5ZY_3: REUSE_ANNOTATE: TRUE; ROOM: PWN-IN
C52 = SC100P50V2JN_1: REUSE_ANNOTATE: TRUE; ROOM: PWN-IN
D1 D3 D4 = 95SQ015_TO_0
D41 = LED_4: REUSE_ANNOTATE: TRUE
FB1-FB7 FB9-FB17 = FB: Part Type: R0402
L1-L3 = INDUCTORS_OF_FERRITE: Power Inductor,4.7uH,0.2,IND_606045; Created by: YWQ; DC Resistor: 0.02ohm; Irms: 3.3A; Isat: 4.97A; Manufacturer: sunlord; Manufacturer PN: SWPA6045S4R7MT; Part Type: POWER_IND; Priority: A; RK PN: SWPA6045S4R7MT; Resonace frequency: 24M; Tolerance: 20%
R11 R14 = RES: Resistor-100K,+/-5%,1/16W-0402; Part Number: 01.0041.00; Part Type: 0402表贴普通电阻; 供应商: 厚声; 规格型号1: 0402WGJ0104TCE
R21 = RESISTOR_0: 通用厚膜电阻,2R,+/-5%,R1210,1/2W.; Created by: YTL; Manufacturer: YAGEO; Manufacturer PN: RC1210JR-072RL; Part Type: 通用厚膜电阻; Priority: A; RK PN: RC1210JR-072RL; Tolerance: 5%; Wattage: 1/2W
R27 R30 R31 = RESISTOR_0: RES 100R Ohm 1/10W 5% 0603 SMD; Installation: ON; Material NO.: R01-101025060; REUSE_ANNOTATE: TRUE
R323 R324 = RESISTOR: RES 4K7 Ohm 1/10W 5% 0603 SMD; Installation: ON; Material NO.: R01-472025060; REUSE_ANNOTATE: TRUE
TP1-TP4 TP6 = TP_1: price: 0
U2 U3 U5 = SCT2450STER
U4 = MP2105_1: REUSE_ANNOTATE: TRUE
U6 = TPS79301: REUSE_ANNOTATE: TRUE
C60-C76 C365-C369 = CAP_NP_1: price: 0.0125
C84 C131 C132 C376 C377 = CAP_NP_0: cap,18.00pF,+/-5%,50V,C0G,C0402; C_Voltage: 6.3V; Created by: JJJ; Dielectric: C0G; Manufacturer: TDK; Manufacturer PN: C1005C0G1H180J050BA; Number: 37; Priority: A; RK PN: C1005C0G1H180J050BA; Tolerance: 5%; Voltage: 50V
D44 = 95SQ015_TO
F1 = FB
J1 = 4_HEADER
K1 = SW_PB_SPST
Q31 = L14C1_TO_2
Q1 Q32 Q33 = NPN_0: S8050,SOT23; Created by: JJJ; Ic: 0.5A; Manufacturer: 长电; Manufacturer PN: S8050_SOT23; Part Type: NPN; Pc: 0.3W; Priority: A; RK PN: S8050; Vceo: 25V
R55 R56 R344-R347 = RESISTOR_1: 通用厚膜电阻,51K,+/-5%,R0402,1/16W.; Created by: YTL; Manufacturer: YAGEO; Manufacturer PN: RC0402JR-0751KL; Part Type: 通用厚膜电阻; Priority: A; RK PN: RC0402JR-0751KL; Tolerance: 5%; Wattage: 1/16W
U8 = STM32F103CBT6_1
U9 U10 = CA-IF1043NF-Q1
X1 X2 = ZTB
C83 C88 = CAP_NP_11: cap,100.00nF,+/-10%,50V,X5R,C0603; Created by: JJJ; Dielectric: X5R; Manufacturer: TDK; Manufacturer PN: C1608X5R1H104K080AA; Part Type: C0603; Priority: A; RK PN: C1608X5R1H104K080AA; Tolerance: 10%; Voltage: 6.3V
C85 C86 = CAP_NP: cap,220.00nF,+/-10%,10V,X5R,C0201; Created by: JJJ; Dielectric: X5R; Manufacturer: TDK; Manufacturer PN: C0603X5R1A224K030BB; Priority: A; RK PN: C0603X5R1A224K030BB; Tolerance: 10%; Voltage: 10V
C96 = CAP_NP_6: cap,100.00nF,+/-10%,10V,X5R,C0402; C_Voltage: 6.3V; Created by: JJJ; Dielectric: X5R; Manufacturer: TDK; Manufacturer PN: C1005X5R1A104K050BA; Number: 37; Priority: A; RK PN: C1005X5R1A104K050BA; Tolerance: 10%; Voltage: 50V
C97-C100 = CAP_NP_1: cap,33.00pF,+/-5%,50V,C0G,C0402; C_Voltage: 6.3V; Created by: JJJ; Dielectric: C0G; Manufacturer: TDK; Manufacturer PN: C1005C0G1H330J050BA; Number: 37; Priority: A; RK PN: C1005C0G1H330J050BA; Tolerance: 5%; Voltage: 50V
C105 C107 = CAP_NP: cap,10.00uF,+/-10%,10V,X5R,C0805; Created by: JJJ; Dielectric: X5R; Manufacturer: TDK; Manufacturer PN: C2012X5R1A106K085AB; Priority: A; RK PN: C2012X5R1A106K085AB; Tolerance: 10%; Voltage: 10V
C106 C108-C110 = CAP_NP: cap,100.00nF,+/-10%,16V,X5R,C0402; C_Voltage: 6.3V; Created by: JJJ; Dielectric: X5R; Manufacturer: TDK; Manufacturer PN: C1005X5R1C104K050BA; Number: 37; Priority: A; RK PN: C1005X5R1C104K050BA; Tolerance: 10%; Voltage: 16V
D6 = DIODE_BI_DIR_TRIG_0: 1-Line, Bi-directional, Transient Voltage Suppressors.0.25pF.; Created by: JJJ; Manufacturer: WillSemi(韦尔半导体); Manufacturer PN: ESD5311N; Part Type: ESD_TVS; Priority: A; RK PN: ESD5311N
D7-D10 = DIODE_BI_DIR_TRIG_0: 1-Line, Bi-directional, Transient Voltage Suppressors.1pF.; Created by: JJJ; Manufacturer: WillSemi(韦尔半导体); Manufacturer PN: ESD5341N; Part Type: ESD_TVS; Priority: A; RK PN: ESD5341N
J2 = M2_M_KEY_2
J4 = MICRO_SIM_0
Q2 Q3 = MOSFET_P: PMOS,WPM3407-3/TR,SOT_23,Id=4.4A,Vds=30V; Created by: JJJ; Id_max: 4.4A; Manufacturer: WillSemi(韦尔半导体); Part Type: PMOS; Pd: 0.9W; Priority: A; VDS: 30V; Vgs: ±20V; Vgsth: 2.0V
Q4 Q5 = NPN: S8050,SOT23; Created by: JJJ; Ic: 0.5A; Manufacturer: 长电; Manufacturer PN: S8050_SOT23; Pc: 0.3W; Priority: A; RK PN: S8050; Vceo: 25V
R59 = RESISTOR_1: 通用厚膜电阻,15K,+/-5%,R0402,1/16W.; Created by: YTL; Manufacturer: YAGEO; Manufacturer PN: RC0402JR-0715KL; Part Type: 通用厚膜电阻; Priority: A; RK PN: RC0402JR-0715KL; Tolerance: 5%; Wattage: 1/16W
R63 R64 R236 R238 R330 R331 = RESISTOR: 通用厚膜电阻,100K,+/-5%,R0402,1/16W.; Created by: YTL; Manufacturer: YAGEO; Manufacturer PN: RC0402JR-07100KL; Part Type: 通用厚膜电阻; Priority: A; RK PN: RC0402JR-07100KL; Tolerance: 5%; Wattage: 1/16W
R65-R68 = RESISTOR: 通用厚膜电阻,10K,+/-5%,R0402,1/16W.; Created by: YTL; Manufacturer: YAGEO; Manufacturer PN: RC0402JR-0710KL; Part Type: 通用厚膜电阻; Priority: A; RK PN: RC0402JR-0710KL; Tolerance: 5%; Wattage: 1/16W
R69 R70 = RESISTOR: 通用厚膜电阻,51K,+/-5%,R0402,1/16W.; Created by: YTL; Manufacturer: YAGEO; Manufacturer PN: RC0402JR-0751KL; Part Type: 通用厚膜电阻; Priority: A; RK PN: RC0402JR-0751KL; Tolerance: 5%; Wattage: 1/16W
C111-C130 C133 = CAP_NP_2: cap,100.00nF,+/-10%,10V,X5R,C0402; C_Voltage: 6.3V; Created by: JJJ; Dielectric: X5R; Manufacturer: TDK; Manufacturer PN: C1005X5R1A104K050BA; Number: 37; Priority: A; RK PN: C1005X5R1A104K050BA; Tolerance: 10%; Voltage: 50V
C134 C137 C138 C143 C150 C152 C154 C161 C163 C165 = CAP_NP_0: cap,10.00uF,+/-10%,25V,X5R,C1206; C_Voltage: 6.3V; Created by: JJJ; Dielectric: X5R; Manufacturer: TDK; Manufacturer PN: C3216X5R1E106K085AC; Part Type: C1206; Priority: A; RK PN: C3216X5R1E106K085AC; Tolerance: 10%; Voltage: 10V
D11-D14 = DIODE_BI_DIR_TRIG_2: 1-Line, Bi-directional, Transient Voltage Suppressors.1pF.; Created by: JJJ; Manufacturer: WillSemi(韦尔半导体); Manufacturer PN: ESD5341N; Part Type: ESD_TVS; Priority: A; RK PN: ESD5341N
J9-J12 = CON7
R71-R87 = RESISTOR_2: 通用厚膜电阻,22R,+/-5%,R0402,1/16W.; Created by: YTL; Manufacturer: YAGEO; Manufacturer PN: RC0402JR-0722RL; Part Type: 通用厚膜电阻; Priority: A; RK PN: RC0402JR-0722RL; Tolerance: 5%; Wattage: 1/16W
U11 = RAPTOR3_3
U12 = SGM2036-3_4.3YN5G_TR
Y1 = OSC
C308 = CAP_NP: cap,1.00uF,+/-10%,16V,X5R,C0402; C_Voltage: 6.3V; Created by: JJJ; Dielectric: X5R; Manufacturer: TDK; Manufacturer PN: C1005X5R1C105K050BC; Priority: A; RK PN: C1005X5R1C105K050BC; Tolerance: 10%; Voltage: 16V
C309 C313 = CAP_NP: cap,100.00nF,+/-10%,10V,X5R,C0201; C_Voltage: 6.3V; Created by: JJJ; Dielectric: X5R; Manufacturer: TDK; Manufacturer PN: C0603X5R1A104K030BC; Number: 37; Priority: A; RK PN: C0603X5R1A104K030BC; Tolerance: 10%; Voltage: 10V
C310 = CAP: 120uF,20V,25mR,SVPF; Created by: YWQ; Dielectric: SVPF; Manufacturer: Panasonic; Manufacturer PN: 20SVPF120M; Part Type: 贴片固态铝电解; Priority: A; RK PN: 20SVPF120M; Tolerance: 20%; Voltage: 20V
C311 = CAP_NP: cap,10.00uF,+/-10%,10V,X5R,C0603; Created by: JJJ; Dielectric: X5R; Manufacturer: TDK; Manufacturer PN: C1608X5R1A106K080AC; Priority: A; RK PN: C1608X5R1A106K080AC; Tolerance: 10%; Voltage: 10V
C312 C314 = CAP_NP: cap,100.00nF,+/-10%,16V,X5R,C0402; Created by: JJJ; Dielectric: X5R; Manufacturer: TDK; Manufacturer PN: C1005X5R1C104K050BA; Priority: A; RK PN: C1005X5R1C104K050BA; Tolerance: 10%; Voltage: 16V
ED13 ED14 ED19 ED20 = DIODE_BI_DIR_TRIG: 1-Line, Bi-directional, Transient Voltage Suppressors.1pF.; Created by: JJJ; Manufacturer: WillSemi(韦尔半导体); Part Type: ESD_TVS; Priority: A
J20 J21 = USB30_TYPE_A_V_2: USB3.0 A型，侧插，母座，插焊; Created by: YWQ; Manufacturer: 祺华电子; Manufacturer Part Number: UA09-SHF-PU03; Part Type: USB Jack; Priority: A; RK PN: UA09-SHF-PU03-30
R228 R230 = RESISTOR: 通用厚膜电阻,2R2,+/-5%,R0402,1/16W.; Created by: YTL; Manufacturer: YAGEO; Manufacturer PN: RC0402JR-072R2L; Part Type: 通用厚膜电阻; Priority: A; RK PN: RC0402JR-072R2L; Tolerance: 5%; Wattage: 1/16W
R229 R231 R240 R242 = RESISTOR: 通用厚膜电阻,0R,+/-5%,R0402,1/16W.; Created by: YTL; Manufacturer: YAGEO; Manufacturer PN: RC0402JR-070RL; Part Type: 通用厚膜电阻; Priority: A; RK PN: RC0402JR-070RL; Tolerance: 5%; Wattage: 1/16W
R232 = RESISTOR: 通用厚膜电阻,0R,+/-5%,R0805,1/8W.; Created by: YTL; Manufacturer: YAGEO; Manufacturer PN: RC0805JR-070RL; Option: DNP; Part Type: 通用厚膜电阻; Priority: A; RK PN: RC0805JR-070RL; Tolerance: 5%; Wattage: 1/8W
R233 R234 = RESISTOR: 通用厚膜电阻,0R,+/-5%,R0201,1/20W.; Created by: YTL; Manufacturer: YAGEO; Manufacturer PN: RC0201JR-070RL; Part Type: 通用厚膜电阻; Priority: A; RK PN: RC0201JR-070RL; Tolerance: 5%; Wattage: 1/20W
R235 = RESISTOR: 通用厚膜电阻,4K7,+/-5%,R0402,1/16W.; Created by: YTL; Manufacturer: YAGEO; Manufacturer PN: RC0402JR-074K7L; Part Type: 通用厚膜电阻; Priority: A; RK PN: RC0402JR-074K7L; Tolerance: 5%; Wattage: 1/16W
SW3 = SW_DIP-4_0
U20 = SWITCH_SY6280: Low Loss Power Distribution Switch; Created by: JJJ; Manufacturer: Silergy（矽力杰）; Manufacturer PN: SY6280AAC; Part Type: Switch; Priority: A; RK PN: SY6280AAC
U28 = SGM7222_1: 1ST PART DESCRIPTION: SGMICRO SGM7222YWQ10/TR ANALOG SWITCH

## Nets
1V2_PLL: C152.1 C153.1 FB13.2 U11.113(VDD1A_PLL)
1V2A_V1: C161.1 C162.1 FB15.2 U11.8(VDD1A1) U11.14(VDD1A2)
1V2A_V2: C163.1 C164.1 FB16.2 U11.20(VDD1A3) U11.26(VDD1A4)
1V2A_V3: C165.1 C166.1 FB17.2 U11.38(VDD1A5) U11.66(VDD1A6)
1V2A_V4: C150.1 C151.1 FB12.2 U11.92(VDD1A7)
1V2D: C154.1 C155.1 C156.1 C157.1 C158.1 C159.1 C160.1 FB14.2 U11.5(VDD1D1) U11.43(VDD1D2) U11.48(VDD1D3) U11.53(VDD1D4) U11.59(VDD1D5) U11.65(VDD1D6) U11.78(VDD1D7) U11.80(VDD1D8) U11.93(VDD1D9) U11.102(VDD1D10) U11.112(VDD1D11) U11.114(VDD1D12) U11.124(VDD1D13)
3V3A_AHD1: C138.1 C139.1 C140.1 C141.1 C142.1 FB10.2 U11.11(VDD3A1) U11.17(VDD3A2) U11.23(VDD3A3) U11.29(VDD3A4) U11.37(VDD3A5) U11.39(VDD3A6) U11.67(VDD3A7) U11.91(VDD3A8)
3V3D_AHD1: C143.1 C144.1 C145.1 C146.1 C147.1 C148.1 C149.1 FB11.2 R86.1 U11.2(VDD3D1) U11.42(VDD3D2) U11.51(VDD3D3) U11.58(VDD3D4) U11.64(VDD3D5) U11.79(VDD3D6) U11.96(VDD3D7) U11.100(VDD3D8) U11.107(VDD3D9) U11.115(VDD3D10) U11.123(VDD3D11) U11.128(VDD3D12)
DGND: C2.2 C3.2 C4.2 C5.2 C6.2 C7.2 C8.2 C9.2 C10.2 C11.2 C12.2 C13.2 C15.2 C16.2 C17.2 C18.2 C19.2 C20.2 C21.2 C22.2 C23.2 C24.2 C25.2 C26.2 C27.2 C28.2 C29.2 C31.2 C32.2 C33.2 C34.2 C35.2 C36.2 C37.2 C38.2 C39.2 C40.2 C41.2 C42.2 C43.2 C44.2 C45.2 C51.2 C52.1 C56.1 C57.2 C60.2 C61.2 C62.2 C63.2 C64.2 C65.2 C66.2 C67.2 C68.2 C69.2 C70.2 C71.2 C72.2 C73.2 C74.2 C75.2 C76.1 C79.2 C80.1 C81.1 C82.1 C83.1 C84.1 C87.2 C88.2 C89.2 C91.2 C92.2 C96.2 C97.2 C98.2 C99.2 C100.2 C105.2 C107.2 C109.2 C110.2 C113.1 C116.1 C117.1 C125.2 C126.1 C127.1 C128.1 C129.1 C131.2 C132.2 C133.1 C134.2 C135.2 C136.2 C137.2 C138.2 C139.2 C140.2 C141.2 C142.2 C143.2 C144.2 C145.2 C146.2 C147.2 C148.2 C149.2 C150.2 C151.2 C152.2 C153.2 C154.2 C155.2 C156.2 C157.2 C158.2 C159.2 C160.2 C161.2 C162.2 C163.2 C164.2 C165.2 C166.2 C167.2 C168.2 C169.2 C170.2 C171.2 C172.2 C173.2 C174.2 C308.2 C310.2 C311.2 C312.2 C314.2 C365.2 C366.2 C367.2 C368.1 C369.2 D1.2(ANODE) D3.2(ANODE) D6.2 D7.2 D8.2 D9.2 D10.2 D11.2 D12.2 D13.2 D14.2 D41.2 ED1.1 ED9.2 ED10.2 ED11.2 ED12.2 ED13.2 ED14.2 ED19.2 ED20.2 J1.4 J2.1(CONFIG_3) J2.3(GND1) J2.5(GND2) J2.11(GND3) J2.21(CONFIG_0) J2.27(GND4) J2.33(GND5) J2.39(GND6) J2.45(GND7) J2.51(GND8) J2.57(GND9) J2.71(GND10) J2.73(GND11) J2.75(CONFIG_2) J2.76(GND12) J2.77(GND13) J2.78(GND14) J4.C5(GND) J4.C8(GND4) J4.C9(GND3) J4.C10(GND2) J4.C11(GND1) J9.2 J9.3 J9.4 J9.6 J9.7 J10.2 J10.3 J10.4 J10.6 J10.7 J11.2 J11.3 J11.4 J11.6 J11.7 J12.2 J12.3 J12.4 J12.6 J12.7 J20.4(GND4) J20.7(GND) J20.10(G1) J20.11(G2) J20.12(G3) J20.13(G4) J21.4(GND4) J21.7(GND) J21.10(G1) J21.11(G2) J21.12(G3) J21.13(G4) K1.1 Q1.2(EMITTER) Q4.2(EMITTER) Q5.2(EMITTER) R6.1 R7.1 R8.1 R14.1 R16.1 R17.1 R18.1 R24.1 R25.1 R26.1 R31.2 R40.1 R56.2 R69.2 R70.2 R73.2 R76.2 R77.1 R78.1 R79.1 R80.1 R81.2 R82.2 R87.1 R235.2 R238.2 R329.1 R331.2 R343.2 R350.1 R352.1 R354.1 SW1.2 SW3.1(A1) TP4.1(TP) TP6.1(TP) U1.40 U1.71 U1.149 U1.150 U2.7(GND1) U2.9(GND2) U3.7(GND1) U3.9(GND2) U4.2(GND) U5.7(GND1) U5.9(GND2) U6.2(GND) U8.12(VSSA) U8.18(VSS_4) U8.31(VSS_1) U8.47(VSS_2) U8.63(VSS_3) U9.2(GND) U10.2(GND) U11.1(VSS1) U11.44(TEST) U11.101(VSS2) U11.103(VSS3) U11.104(VSS4) U11.105(VSS5) U11.106(VSS6) U11.108(VSS7) U11.109(VSS8) U11.110(VSS9) U11.111(VSS10) U11.118(VSS11) U11.119(VSS12) U11.120(VSS13) U11.121(VSS14) U11.122(VSS15) U11.125(VSS16) U11.126(VSS17) U11.127(VSS18) U11.129(PGND) U12.1(GND) U20.2(GND) U28.4(GND) Y1.2(GND) ; also on sheet 7 8 9 10 11 12 13 14 15 16 17
VCC1V2: C136.1 C137.1 FB12.1 FB13.1 FB14.1 FB15.1 FB16.1 FB17.1 U12.2(OUT) U12.4(TAB) ; also on sheet 7
VCC3V3_SYS: C26.1 C107.1 C108.1 C134.1 C135.1 C365.1 FB4.2 FB5.2 FB9.1 FB10.1 FB11.1 Q3.2(SOURCE) R11.1 R36.1 R64.1 R323.2 R324.2 TP2.1(TP) U4.1(IN) U12.3(IN) U28.9(VCC) ; also on sheet 7 8 9 10 11 12 14 15 16 17
VCC3V9_5G: C105.1 C106.1 FB1.2 FB2.2 FB3.2 Q2.2(SOURCE) R63.1 R350.2 TP1.1(TP) U1.143 U1.144 U1.145 U1.146 ; also on sheet 9
VCC5V0_SYS: C56.2 C75.1 C308.1 C366.1 C367.1 C369.1 FB6.2 FB7.2 R30.1 R232.1 TP3.1(TP) U6.1(IN) U9.3(VCC) U9.10(VSUP) U10.3(VCC) U10.10(VSUP) U20.5(IN) ; also on sheet 8 16
VCC5V0_USB30_HOST0: C310.1 C311.1 C312.1 J20.1(VBUS) R232.2 R236.1 U20.1(VOUT)
VCC_1V8: C27.1 R14.2 R347.1 U4.5(OUT) ; also on sheet 8 9 10 13 15
VCC_DCIN: C8.1 C9.1 C10.1 C11.1 C21.1 C22.1 C23.1 C24.1 C37.1 C38.1 C39.1 C40.1 C41.1 C42.1 C167.1 C168.1 C169.1 C170.1 C171.1 C172.1 C173.1 C174.1 D4.1(CATHODE) J9.1 J10.1 J11.1 J12.1 R13.2 R22.2 U2.2(VIN) U3.2(VIN) U5.2(VIN) ; also on sheet 7
VCC_IN: D4.2(ANODE) R21.1 ; also on sheet 15
VINN1: C120.1 R73.1
VINN2: C121.1 R76.1
VINN3: C123.1 R81.1
VINN4: C112.1 R82.1
VINP1: C119.1 R71.2 R78.2
VINP1_COAX: D11.1 J9.5 R71.1
VINP2: C111.1 R74.2 R77.2
VINP2_COAX: D12.1 J10.5 R74.1
VINP3: C122.1 R72.2 R79.2
VINP3_COAX: D14.1 J11.5 R72.1
VINP4: C124.1 R75.2 R80.2
VINP4_COAX: D13.1 J12.5 R75.1
5G_3V3: Q3.3(DRAIN) R52.2 R53.2 R54.2 R345.1
5G_3V9: C79.1 C80.2 C81.2 C82.2 C83.2 C87.1 C88.1 C89.1 C91.1 C92.1 D6.1 J2.2(VCC1) J2.4(VCC2) J2.70(VCC3) J2.72(VCC4) J2.74(VCC5) Q2.3(DRAIN)
5G_PWR_OFF: J2.6(POWER_OFF#) ; also on sheet 16
5G_PWRER_CTR: R67.1 ; also on sheet 16
5G_RESET: R55.1 ; also on sheet 16
5G_USB_DM: J2.9(USB_DM) U28.5(D-)
5G_USB_DP: J2.7(USB_DP) U28.3(D+)
5G_VBUS: J21.1(VBUS) R330.1
5G_W_DISABLE1#: J2.8(W_DISABLE1#) R51.1
5G_WAKE_MCU: Q32.3(COLLECTOR) R345.2 U8.33(PB12)
5G_WAKE_ON_WAN: J2.23(WAKE_ON_WAN#) Q32.2(EMITTER)
5G_WAKEUP_IN: J2.38(WAKEUP_IN) U1.214
5G_WWAN_LED#: J2.10(WWAN_LED#) ; also on sheet 9
27M_CLK_XI: C132.1 R83.2 R85.1 Y1.3(OUT)
ACC_CHECK: R39.2 ; also on sheet 15 16
AHD_I2C_SCL: U1.99 U11.49(SCL) ; also on sheet 7
AHD_I2C_SDA: U1.98 U11.50(SDA) ; also on sheet 7
AHD_RSTN: U1.95 U11.47(RSTB) ; also on sheet 7
ARM_CAN2_EN: U1.100 ; also on sheet 16
ARM_CAN2_nSTB: U1.97 ; also on sheet 16
ARM_CAN3_nSTB: U1.92 ; also on sheet 16
BOOT: D44.2(CATHODE) ; also on sheet 15
BOOT0: Q31.3(COLLECTOR) R343.1 U8.60(BOOT0)
BT_RST: U1.233 ; also on sheet 9
BT_WAKE_HOST_H: U1.216 ; also on sheet 9
CAN1_RX: U8.61(PB8) U9.4(RXD)
CAN1_TX: U8.62(PB9) U9.1(TXD)
CAN2_RX: U8.57(PB5) U10.4(RXD)
CAN2_RX_M0: U1.96 ; also on sheet 16
CAN2_TX: U8.58(PB6) U10.1(TXD)
CAN2_TX_M0: U1.93 ; also on sheet 16
CAN_WAKEUP_0: R351.1 R352.2 U8.37(PC6)
CAN_WAKEUP_1: R353.1 R354.2 U8.39(PC8)
CAN_WAKEUP_2: U8.34(PB13) ; also on sheet 16
CAN_WAKEUP_3: U8.35(PB14) ; also on sheet 16
DEBUG_DM: R240.2 U28.6(HSD2-)
DEBUG_DM0: ED19.1 J21.2(D-) R240.1
DEBUG_DP: R242.2 U28.2(HSD2+)
DEBUG_DP0: ED20.1 J21.3(D+) R242.1
ETH0_REFCLKO_25M: U1.227 ; also on sheet 10
ETH1_REFCLKO_25M: U1.156 ; also on sheet 11
GMAC0_MCLKINOUT: U1.223 ; also on sheet 10
GMAC0_MDC: U1.250 ; also on sheet 10
GMAC0_MDIO: U1.236 ; also on sheet 10
GMAC0_RSTn_L: U1.94 ; also on sheet 10
GMAC0_RXCLK: U1.162 ; also on sheet 10
GMAC0_RXD0: U1.245 ; also on sheet 10
GMAC0_RXD1: U1.237 ; also on sheet 10
GMAC0_RXD2: U1.165 ; also on sheet 10
GMAC0_RXD3: U1.164 ; also on sheet 10
GMAC0_RXDV_CRS: U1.228 ; also on sheet 10
GMAC0_TXCLK: U1.163 ; also on sheet 10
GMAC0_TXD0: U1.229 ; also on sheet 10
GMAC0_TXD1: U1.225 ; also on sheet 10
GMAC0_TXD2: U1.166 ; also on sheet 10
GMAC0_TXD3: U1.167 ; also on sheet 10
GMAC0_TXEN: U1.224 ; also on sheet 10
GMAC1_MCLKINOUT: U1.141 ; also on sheet 11
GMAC1_MDC: U1.153 ; also on sheet 11
GMAC1_MDIO: U1.152 ; also on sheet 11
GMAC1_RSTn_L: U1.148 ; also on sheet 11
GMAC1_RXCLK: U1.159 ; also on sheet 11
GMAC1_RXD0: U1.160 ; also on sheet 11
GMAC1_RXD1: U1.157 ; also on sheet 11
GMAC1_RXD2: U1.171 ; also on sheet 11
GMAC1_RXD3: U1.174 ; also on sheet 11
GMAC1_RXDV_CRS: U1.158 ; also on sheet 11
GMAC1_TXCLK: U1.161 ; also on sheet 11
GMAC1_TXD0: U1.151 ; also on sheet 11
GMAC1_TXD1: U1.147 ; also on sheet 11
GMAC1_TXD2: U1.173 ; also on sheet 11
GMAC1_TXD3: U1.172 ; also on sheet 11
GMAC1_TXEN: U1.142 ; also on sheet 11
HDMI0_TX0N_PORT/eDP0_TX_D0N: U1.16 ; also on sheet 8
HDMI0_TX0P_PORT/eDP0_TX_D0P: U1.17 ; also on sheet 8
HDMI0_TX1N_PORT/eDP0_TX_D1N: U1.18 ; also on sheet 8
HDMI0_TX1P_PORT/eDP0_TX_D1P: U1.19 ; also on sheet 8
HDMI0_TX2N_PORT/eDP0_TX_D2N: U1.20 ; also on sheet 8
HDMI0_TX2P_PORT/eDP0_TX_D2P: U1.21 ; also on sheet 8
HDMI0_TX3N_PORT/eDP0_TX_D3N: U1.14 ; also on sheet 8
HDMI0_TX3P_PORT/eDP0_TX_D3P: U1.15 ; also on sheet 8
HDMI0_TX_SBDN/eDP0_TX_AUXN: U1.12 ; also on sheet 8
HDMI0_TX_SBDP/eDP0_TX_AUXP: U1.13 ; also on sheet 8
HDMITX0_CEC_M0: U1.170 ; also on sheet 8
HDMITX0_HPDIN: U1.231 ; also on sheet 8
HDMITX0_SCL_M0: U1.168 ; also on sheet 8
HDMITX0_SDA_M0: U1.169 ; also on sheet 8
HOST_WAKE_BT_H: U1.218 ; also on sheet 9
I2C4_SCL_M1_GPIO2-B5: J2.25(I2C_CLK) U1.211
I2C4_SDA_M1_GPIO2-B4: J2.68(I2C_DATA) U1.212
I2S0_LRCK_TX: U1.220 ; also on sheet 13
I2S0_MCLK: U1.222 ; also on sheet 13
I2S0_SCLK_TX: U1.219 ; also on sheet 13
I2S0_SDI0: U1.239 ; also on sheet 13
I2S0_SDO0: U1.221 ; also on sheet 13
MCU_3V3: C46.1 C51.1 C52.2 C66.1 C67.1 C68.1 C69.1 C70.1 C71.1 C72.1 C76.2 C368.2 C377.1 F1.1 J1.1 Q31.2(EMITTER) R27.1 R341.1 R346.1 U6.6(OUT) U8.1(VBAT) U8.19(VDD_4) U8.32(VDD_1) U8.48(VDD_2) U8.64(VDD_3) U9.5(VIO) U10.5(VIO)
MCU_CAN0_EN: U8.38(PC7) U9.6(EN)
MCU_CAN0_H: R44.1 ; also on sheet 15
MCU_CAN0_L: R45.1 ; also on sheet 15
MCU_CAN0_nSTB: U8.36(PB15) U9.14(nSTB)
MCU_CAN1_EN: U8.41(PA8) U10.6(EN)
MCU_CAN1_H: R332.1 ; also on sheet 15
MCU_CAN1_L: R334.1 ; also on sheet 15
MCU_CAN1_nSTB: U8.40(PC9) U10.14(nSTB)
MCU_DEBUG_RX: U8.43(PA10) ; also on sheet 16
MCU_DEBUG_TX: U8.42(PA9) ; also on sheet 16
MCU_RST: C62.1 K1.2 R36.2 U8.7(NRST)
MCU_WAKEUP_RK3588: Q33.2(EMITTER) U8.44(PA11)
MIPI_CSI0_RX_CLK0N: U1.136 U11.85(TX0_CN)
MIPI_CSI0_RX_CLK0P: U1.135 U11.86(TX0_CP)
MIPI_CSI0_RX_D0N: U1.140 U11.81(TX0_DN0)
MIPI_CSI0_RX_D0P: U1.139 U11.82(TX0_DP0)
MIPI_CSI0_RX_D1N: U1.138 U11.83(TX0_DN1)
MIPI_CSI0_RX_D1P: U1.137 U11.84(TX0_DP1)
MIPI_CSI0_RX_D2N: U1.134 U11.87(TX0_DN2)
MIPI_CSI0_RX_D2P: U1.133 U11.88(TX0_DP2)
MIPI_CSI0_RX_D3N: U1.132 U11.89(TX0_DN3)
MIPI_CSI0_RX_D3P: U1.131 U11.90(TX0_DP3)
MIPI_CSI1_RX_CLK0N: U1.125 ; also on sheet 7
MIPI_CSI1_RX_CLK0P: U1.126 ; also on sheet 7
MIPI_CSI1_RX_D0N: U1.129 ; also on sheet 7
MIPI_CSI1_RX_D0P: U1.130 ; also on sheet 7
MIPI_CSI1_RX_D1N: U1.127 ; also on sheet 7
MIPI_CSI1_RX_D1P: U1.128 ; also on sheet 7
MIPI_CSI1_RX_D2N: U1.123 ; also on sheet 7
MIPI_CSI1_RX_D2P: U1.124 ; also on sheet 7
MIPI_CSI1_RX_D3N: U1.121 ; also on sheet 7
MIPI_CSI1_RX_D3P: U1.122 ; also on sheet 7
OSC_IN: C63.1 R38.1 U8.5(PD0-OSC_IN) X2.1
OSC_OUT: C64.1 R38.2 U8.6(PD1-OSC_OUT) X2.2
PCIE20_0_RXN/SATA30_0_RXN: U1.184 ; also on sheet 17
PCIE20_0_RXP/SATA30_0_RXP: U1.183 ; also on sheet 17
PCIE20_0_TXN/SATA30_0_TXN: U1.181 ; also on sheet 17
PCIE20_0_TXP/SATA30_0_TXP: U1.182 ; also on sheet 17
PCIE20_2_REFCLKN: J2.53(PCIE_REFCLK_M) U1.189
PCIE20_2_REFCLKP: J2.55(PCIE_REFCLK_P) U1.190
PCIE20_2_RXN/SATA30_2_RXN: J2.41(PCIE_TX_M) U1.185
PCIE20_2_RXP/SATA30_2_RXP: J2.43(PCIE_TX_P) U1.186
PCIE20_2_TXN/SATA30_2_TXN: C85.1 U1.187
PCIE20_2_TXP/SATA30_2_TXP: C86.1 U1.188
PCIEX1_1_CLKREQn_M1_L: J2.52(PCIE_CLKREQ_N) R53.1 ; also on sheet 16
PCIEX1_1_PERSTn_M1_L: J2.50(PCIE_RST_N) R52.1 ; also on sheet 16
PCIEX1_1_WAKEn_M1_L: J2.54(PCIE_WAKE_N) R54.1 ; also on sheet 16
POWER_EN: R6.2 U2.3(EN) U8.21(PA5)
RESET_L: R2.2 ; also on sheet 15
RFFE_VIO_1V8: C376.1 J2.65(RFFE_VIO_1V8) R51.2 R68.1 R344.1
RM500U_RESET: C84.2 J2.67(RESET#) Q1.3(COLLECTOR)
RTC_IN: C60.1 U8.3(PC14-OSC32_IN) X1.1
RTC_OUT: C61.1 U8.4(PC15-OSC32_OUT) X1.2
RUN_LED: D41.4 U8.45(PA12)
SARADC_VIN1_KEY/RECOVERY: ED1.2 R1.1 U1.1
SCL_CODEC: U1.255 ; also on sheet 13
SD_CLK: U1.11 ; also on sheet 9
SDA_CODEC: U1.256 ; also on sheet 13
SDMMC0_CMD: U1.10 ; also on sheet 9
SDMMC0_D0: U1.6 ; also on sheet 9
SDMMC0_D1: U1.7 ; also on sheet 9
SDMMC0_D2: U1.8 ; also on sheet 9
SDMMC0_D3: U1.9 ; also on sheet 9
SWCLK: J1.2 U8.49(PA14)
SWDIO: J1.3 U8.46(PA13)
TYPEC0_OTG_DM: R228.2 U1.58
TYPEC0_OTG_DP: R230.2 U1.57
TYPEC0_SSRX1N: R233.1 U1.66
TYPEC0_SSRX1P: R234.1 U1.65
TYPEC0_SSTX1N: C309.1 U1.70
TYPEC0_SSTX1P: C313.1 U1.69
TYPEC0_USB20_OTG_ID: SW3.2(B1) U1.252
TYPEC0_USB20_VBUSDET: C314.1 R236.2 R238.1 U1.60
UART1_RX_M1: J2.64(UART_TXD) U1.240
UART1_TX_M1: J2.62(UART_RXD) U1.241
UART2_RX_M0_DEBUG: U1.3 ; also on sheet 16
UART2_TX_M0_DEBUG: U1.2 ; also on sheet 16
UART6_CTSN_M1: U1.230 ; also on sheet 9
UART6_RTSN_M1: U1.232 ; also on sheet 9
UART6_RX_M1: U1.235 ; also on sheet 9
UART6_TX_M1: U1.234 ; also on sheet 9
UART7_RX_M1: U1.155 ; also on sheet 15
UART7_TX_M1: U1.154 ; also on sheet 15
UART9_RX_M1: U8.16(PA2) ; also on sheet 16
UART9_TX_M1: U8.17(PA3) ; also on sheet 16
USB20_HOST0_DM: U1.42 U28.7(HSD1-)
USB20_HOST0_DP: U1.41 U28.1(HSD1+)
USB20_HOST1_DM: U1.46 ; also on sheet 12
USB20_HOST1_DP: U1.45 ; also on sheet 12
USB30_HOST0_SSRXN: ED12.1 J20.5(RX-) R233.2
USB30_HOST0_SSRXP: ED11.1 J20.6(RX+) R234.2
USB30_HOST0_SSTXN: C309.2 ED10.1 J20.8(TX-)
USB30_HOST0_SSTXP: C313.2 ED9.1 J20.9(TX+)
USB30_OTG0_DM: ED13.1 J20.2(D-) R229.1
USB30_OTG0_DP: ED14.1 J20.3(D+) R231.1
USB_HOST_PWREN_H: U1.249 U20.4(EN)
USIM1_CLK: C100.1 D7.1 J2.32(USIM1_CLK) J4.C3(CLK)
USIM1_DATA: C99.1 D10.1 J2.34(USIM1_DATA) J4.C7(I/O) R59.2
USIM1_RST: C98.1 D8.1 J2.30(USIM1_RST) J4.C2(RST)
USIM1_VDD: C96.1 C97.1 D9.1 J2.36(USIM1_VDD) J4.C1(VCC) R59.1
V_DDA: C65.1 C73.1 C74.1 F1.2 U8.13(VDDA)
WAKEUP_RK3588: Q33.3(COLLECTOR) R347.2 U1.254
WIFI_REG_ON: U1.215 ; also on sheet 9
WIFI_WAKE_HOST: U1.246 ; also on sheet 9
XO: R83.1 R84.2 U11.95(XO)
N16962772: C119.2 U11.12(VIN1)
N16962795: C120.2 U11.13(VCM1)
N16962816: C111.2 U11.18(VIN2)
N16962837: C121.2 U11.19(VCM2)
N16962856: C122.2 U11.24(VIN3)
N16962873: C123.2 U11.25(VCM3)
N16962896: C124.2 U11.30(VIN4)
N16962917: C112.2 U11.31(VCM4)
N16962947: C113.2 C114.1 U11.9(REFT1)
N16962991: C114.2 C127.2 U11.10(REFB1)
N16963001: C115.1 C126.2 U11.15(REFT2)
N16963037: C115.2 C116.2 U11.16(REFB2)
N16963051: C117.2 C118.1 U11.21(REFT3)
N16963101: C118.2 C129.2 U11.22(REFB3)
N16963115: C128.2 C130.1 U11.27(REFT4)
N16963147: C130.2 C133.2 U11.28(REFB4)
N16963702: R85.2 U11.94(SYS_CLK_XI)
N16963854: R86.2 U11.45(SA0)
N16963899: R87.2 U11.46(SA1)
N16974815: C125.1 FB9.2 Y1.4(VCC)
N16974853: C131.1 R84.1 Y1.1(NC)
N17187928: R235.1 U20.3(OCB)
N17430388: C14.1 D1.1(CATHODE) L2.1 U3.8(PH)
N17430409: C15.1 C16.1 C17.1 C18.1 C19.1 C20.1 FB4.1 FB5.1 L2.2 R9.2
N17430604: C14.2 U3.1(BOOT)
N17430621: R9.1 R12.2
N17430780: R13.1 R16.2 U3.3(EN)
N17430784: C28.1 R15.2 U3.6(COMP)
N17430790: R12.1 R18.2 U3.5(VSENSE)
N17430830: R17.2 U3.4(RT)
N17430874: C29.1 R15.1
N17430974: C30.1 D3.1(CATHODE) L3.1 U5.8(PH)
N17430995: C31.1 C32.1 C33.1 C34.1 C35.1 C36.1 FB6.1 FB7.1 L3.2 R19.2
N17431217: C30.2 U5.1(BOOT)
N17431234: R19.1 R20.2
N17431430: R22.1 R24.2 U5.3(EN)
N17431436: C44.1 R23.2 U5.6(COMP)
N17431442: R20.1 R26.2 U5.5(VSENSE)
N17431605: C45.1 R23.1
N17445345: C43.1 R21.2
N17445910: C1.1 L1.1 U2.8(PH)
N17445924: C2.1 C3.1 C4.1 C5.1 C6.1 C7.1 FB1.1 FB2.1 FB3.1 L1.2 R3.2
N17446104: C1.2 U2.1(BOOT)
N17446121: R3.1 R4.2
N17446263: C12.1 R5.2 U2.6(COMP)
N17446269: R4.1 R8.2 U2.5(VSENSE)
N17446309: R7.2 U2.4(RT)
N17446353: C13.1 R5.1
N17457092: R40.2 U8.28(PB2)
N17467708: R30.2 U6.3(EN)
N17467712: C46.2 R27.2 R31.1 U6.5(FB)
N17467744: C57.1 U6.4(BYPASS)
N17473177: C85.2 J2.47(PCIE_RX_M)
N17473180: C86.2 J2.49(PCIE_RX_P)
N17481320: Q1.1(BASE) R55.2 R56.1
N17534566: C25.1 R11.2 U4.3(EN)
N17570124: R228.1 R229.2
N17570191: R230.1 R231.2
N17622103: C108.2 Q3.1(GATE) R64.2 R66.1
N17622132: Q5.3(COLLECTOR) R66.2
N17622163: C110.1 Q5.1(BASE) R68.2 R70.1
N17719071: R2.1 U1.59
N17720124: R1.2 SW1.1
N17732255: C106.2 Q2.1(GATE) R63.2 R65.1
N17732284: Q4.3(COLLECTOR) R65.2
N17732315: C109.1 Q4.1(BASE) R67.2 R69.1
N17733329: R39.1 U8.23(PA7)
N17887677: D41.3 R323.1
N17887693: D41.1 R324.1
N17891340: R329.2 U28.8(OE_N)
N17893373: R330.2 R331.1 U28.10(S)
N17901873: R43.2 R44.2 U9.13(CANH)
N17901877: R43.1 R45.2 U9.12(CANL)
N17904447: R332.2 R333.2 U10.13(CANH)
N17904489: R333.1 R334.2 U10.12(CANL)
N17918762: D44.1(ANODE) R341.2 R342.1
N17918800: Q31.1(BASE) R342.2
N17919694: C376.2 Q32.1(BASE) R344.2
N17920327: C377.2 Q33.1(BASE) R346.2
N18155986: R25.2 U5.4(RT)
N18177282: R351.2 U9.7(INH)
N18177600: R353.2 U10.7(INH)

Not connected (* = marked no-connect by the designer): J2 20(PCM_CLK)* 22(PCM_DIN)* 24(PCM_DOUT)* 26(B_CODE_OUT)* 28(PCM_SYNC)* 29(USB_SS_TX_M)* 31(USB_SS_TX_P)* 35(USB_SS_RX_M)* 37(USB_SS_RX_P)* 40(USIM2_DET)* 42(USIM2_DATA)* 44(USIM2_CLK)* 46(USIM2_RST)* 48(USIM2_VDD)* 56(RESERVED1)* 58(RESERVED2)* 59(SPI_CS)* 60(SPI_DIN)* 61(SPI_CLK)* 63(SPI_DOUT)* 66(USIM1_DET)* 69(CONFIG_1)*; J4 C6(VPP)*; J21 5(RX-)* 6(RX+)* 8(TX-)* 9(TX+)*; U1 4* 5* 22* 23* 24* 25* 26* 27* 28* 29* 30* 31* 32* 33* 34* 35* 36* 37* 38* 39* 43* 44* 47* 48* 49* 50* 51* 52* 53* 54* 55* 56* 61* 62* 63* 64* 67* 68* 72* 73* 74* 75* 76* 77* 78* 79* 80* 81* 82* 83* 84* 85* 86* 87* 88* 89* 90* 91* 101* 102* 103* 104* 105* 106* 107* 108* 109* 110* 111* 112* 113* 114* 115* 116* 117* 118* 119* 120* 175* 176* 177* 178* 179* 180* 191* 192* 193* 194* 195* 196* 197* 198* 199* 200* 201* 202* 203* 204* 205* 206* 207* 208* 209* 210* 213* 217* 226* 238* 242* 243* 244* 247* 248* 251* 253*; U4 4(NC)*; U8 2(PC13-TAMPER-RTC)* 8(PC0)* 9(PC1)* 10(PC2)* 11(PC3)* 14(PA0-WKUP)* 15(PA1)* 20(PA4)* 22(PA6)* 24(PC4)* 25(PC5)* 26(PB0)* 27(PB1)* 29(PB10)* 30(PB11)* 50(PA15)* 51(PC10)* 52(PC11)* 53(PC12)* 54(PD2)* 55(PB3)* 56(PB4)* 59(PB7)*; U9 8(nFAULT)* 9(WAKE)* 11(NC)*; U10 8(nFAULT)* 9(WAKE)* 11(NC)*; U11 3(COAX4)* 4(COAX3)* 6(COAX2)* 7(COAX1)* 32(AIN1)* 33(AIN2)* 34(AIN3)* 35(AIN4)* 36(MICIN)* 40(AOUT)* 41(VREF)* 52(ADATA_CASO)* 54(ACLK_PB)* 55(ASYNC_PB)* 56(ADATA_PB)* 57(ACLK_REC)* 60(ASYNC_REC)* 61(ADATA_REC)* 62(ADATA_SP)* 63(IRQ)* 68(TX1_DP3)* 69(TX1_DN3)* 70(TX1_DP2)* 71(TX1_DN2)* 72(TX1_CP)* 73(TX1_CN)* 74(TX1_DP1)* 75(TX1_DN1)* 76(TX1_DP0)* 77(TX1_DN0)* 97(NC4)* 98(NC3)* 99(ADATA_CASI)* 116(NC2)* 117(NC1)*

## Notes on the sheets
sheet 1
- USB3.0 OTG0
- Cj<=0.3pF
- Ilim(A)=6800/Rset(ohm)
- OTG配置：
  1.默认OTG为上拉,此时为DEVICE;
  2.拨到到接地,此时为HOST.
- 5G固件升级口
sheet 2
- UART9_CTSN_M0_BT-BT-GPIO4-C5
- I2C7_SDA_M0_CODEC--GPIO1-D1
- I2C7_SCL_M0_CODEC-GPIO1-D0
- MIPI_CAM1_CLKOUT-GPIO1-B6
- MIPI_CAM2_CLKOUT-GPIO1-B7
- MIPI_CAM1/2_RESET-GPIO1-A3
- MIPI_CAM3/4_RESET_GPIO2-B6
- UART9_RTSn_M0_BT-GPIO4-C4
- I2C2_SDA_M4_MIPI-GPIO1-A0
- I2C2_SCL_M4_MIPI-GPIO1-A1
- I2S2_SCLK_M0_BT-GPIO2-B7
- I2S2_LRCK_M0_BT-GPIO2-C0
- USB_HUB_RESET-GPIO3_B2
- UART9_TX_M0_BT-GPIO2-C2
- MIPI_CAM2_PDN-GPIO1-A4
- MIPI_CAM1_PDN-GPIO1-A2
- I2S2_SDI_M0_BT-GPIO2-C3
- I2S2_SDO_M0_BT-GPIO4-C3
- HOST_WAKE_BT_GPIO0_C5
- GSENSOR_INT_GPIO4-C2
- I2S0_LRCK_TX-GPIO1-C5
- I2S0_SCLK_TX-GPIO1-C3
- BT_WAKE_HOST_GPIO0_A0
- WIFI_REG_ON_GPIO0_C4
- I2C6_SDA_M0-GPIO0_C7
- BT_REG_ON_GPIO0_C6
- LCD_BL_EN_GPIO2-C1
- I2S0_SDI0--GPIO1-D4
- I2S0_MCLK-GPIO1-C2
- I2S0_SDO0-GPIO1-C7
- GMAC1_RXD3-GPIO3_A3
- GMAC1_TXD2-GPIO3_A0
- GMAC1_TXD3-GPIO3_A1
- GMAC1_RXD2-GPIO3_A2
- HDMITX0_CEC_M0-GPIO4-C1
- HDMITX0_SDA_M0-GPIO4-C0
- HDMITX0_SCL_M0-GPIO4-B7
- SDIO_CMD_M0_WIFI
- SDIO_D3_M0_WIFI
- SDIO_D0_M0_WIFI
- SDIO_D1_M0_WIFI
- SDIO_CLK_M0_WIFI
- SDIO_D2_M0_WIFI
- GMAC1_TXCLK-GPIO3_A4
- GMAC1_RXD0-GPIO3_A7
- GMAC1_RXCLK-GPIO3_A5
- GMAC1_RXDV-GPIO3_B1
- ETH1_REFCLKO_25M-GPIO3_A6
- GMAC1_RXD1-GPIO3_B0
- TP_RST-GPIO3_C1
- TP_INT-GPIO3_C0
- GMAC1_MDC-GPIO3_C2
- GMAC1_MDIO-GPIO3_C3
- GMAC1_TXD0-GPIO3_B3
- GMAC1_RSTN_L-GPIO3_C0
- GMAC1_TXD1-GPIO3_B4
- GMAC1_TXEN-GPIO3_B6
- GMAC1_MCLKINOUT-GPIO3_B7
- I2C5_SDA_M0_TP-GPIO3_D0
- I2C5_SCL_M0_TP-GPIO3_C7
- HDMIIRX_HPDOUT-GPIO3_D4
- HDMI_RX_CEC-GPIO3_D1
- HDMITX1_SDA-GPIO3_C5
- HDMI_RX_SCL-GPIO3_D2
- HDMI_RX_SDA-GPIO3_D3
- HDMITX1_CEC-GPIO3_C4
- HDMITX1_SCL-GPIO3_C6
sheet 3
- 核心板和5G电源
- 1.8V电源
- 3.3V系统电源
- 5V系统电源
- 输入电源
- XT100UF50V90RV0067
- MCU电源
sheet 4
- 单片机
- DT-26
- NX3225GB
- 5个唤醒MCU唤醒源
- 1.3A,120ohm@100M
- CAN0通讯
- CAN1通讯
sheet 5
- 5G插座-M.2
- 1.为了便于产品安装 ,需要将5G模组天线转换
  为4合1同轴电缆接口；
  2.IPEX插座距离5G模组IPEX天线插座距离保持4cm距离.
sheet 6
- ∝ VIDEO  INPUT
  1. VINP1 and VINN1 : Same Length  and  Shortest distance
  2. REFT1 and REFB1 : Same Length  and  Shortest distance
  3. You must be the same length and shortest distance by channel when routing signals
  4. Ground shielding
- ∝ POWER
  - DVDD33, AVDD33, DVDD12, AVDD12, AVDD12_PLL
  1. Thicker than normal signal
  2. Ground shielding
- 输入模拟视频
- 有源晶振
- ∝ Capacitor Place Top
  - This parts are important elements
  It should be place top
- 1.2V电源
- I2C add 0x62
- 电源引脚
- NVP6188A
